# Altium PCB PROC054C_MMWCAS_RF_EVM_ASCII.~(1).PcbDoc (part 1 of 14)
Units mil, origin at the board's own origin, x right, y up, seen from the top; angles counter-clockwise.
Board outline 6299.21 x 5370.07 mil, 8 copper layers (L1 TOP, L2 GND, L3 SIGNAL 1, L4 GND, L5 SIGNAL 2, L6 SIGNAL 3, L7 GND, L8 BOTTOM), stack 53.5 mil thick; 775 components, 552 nets, 2648 pads, 7845 vias.
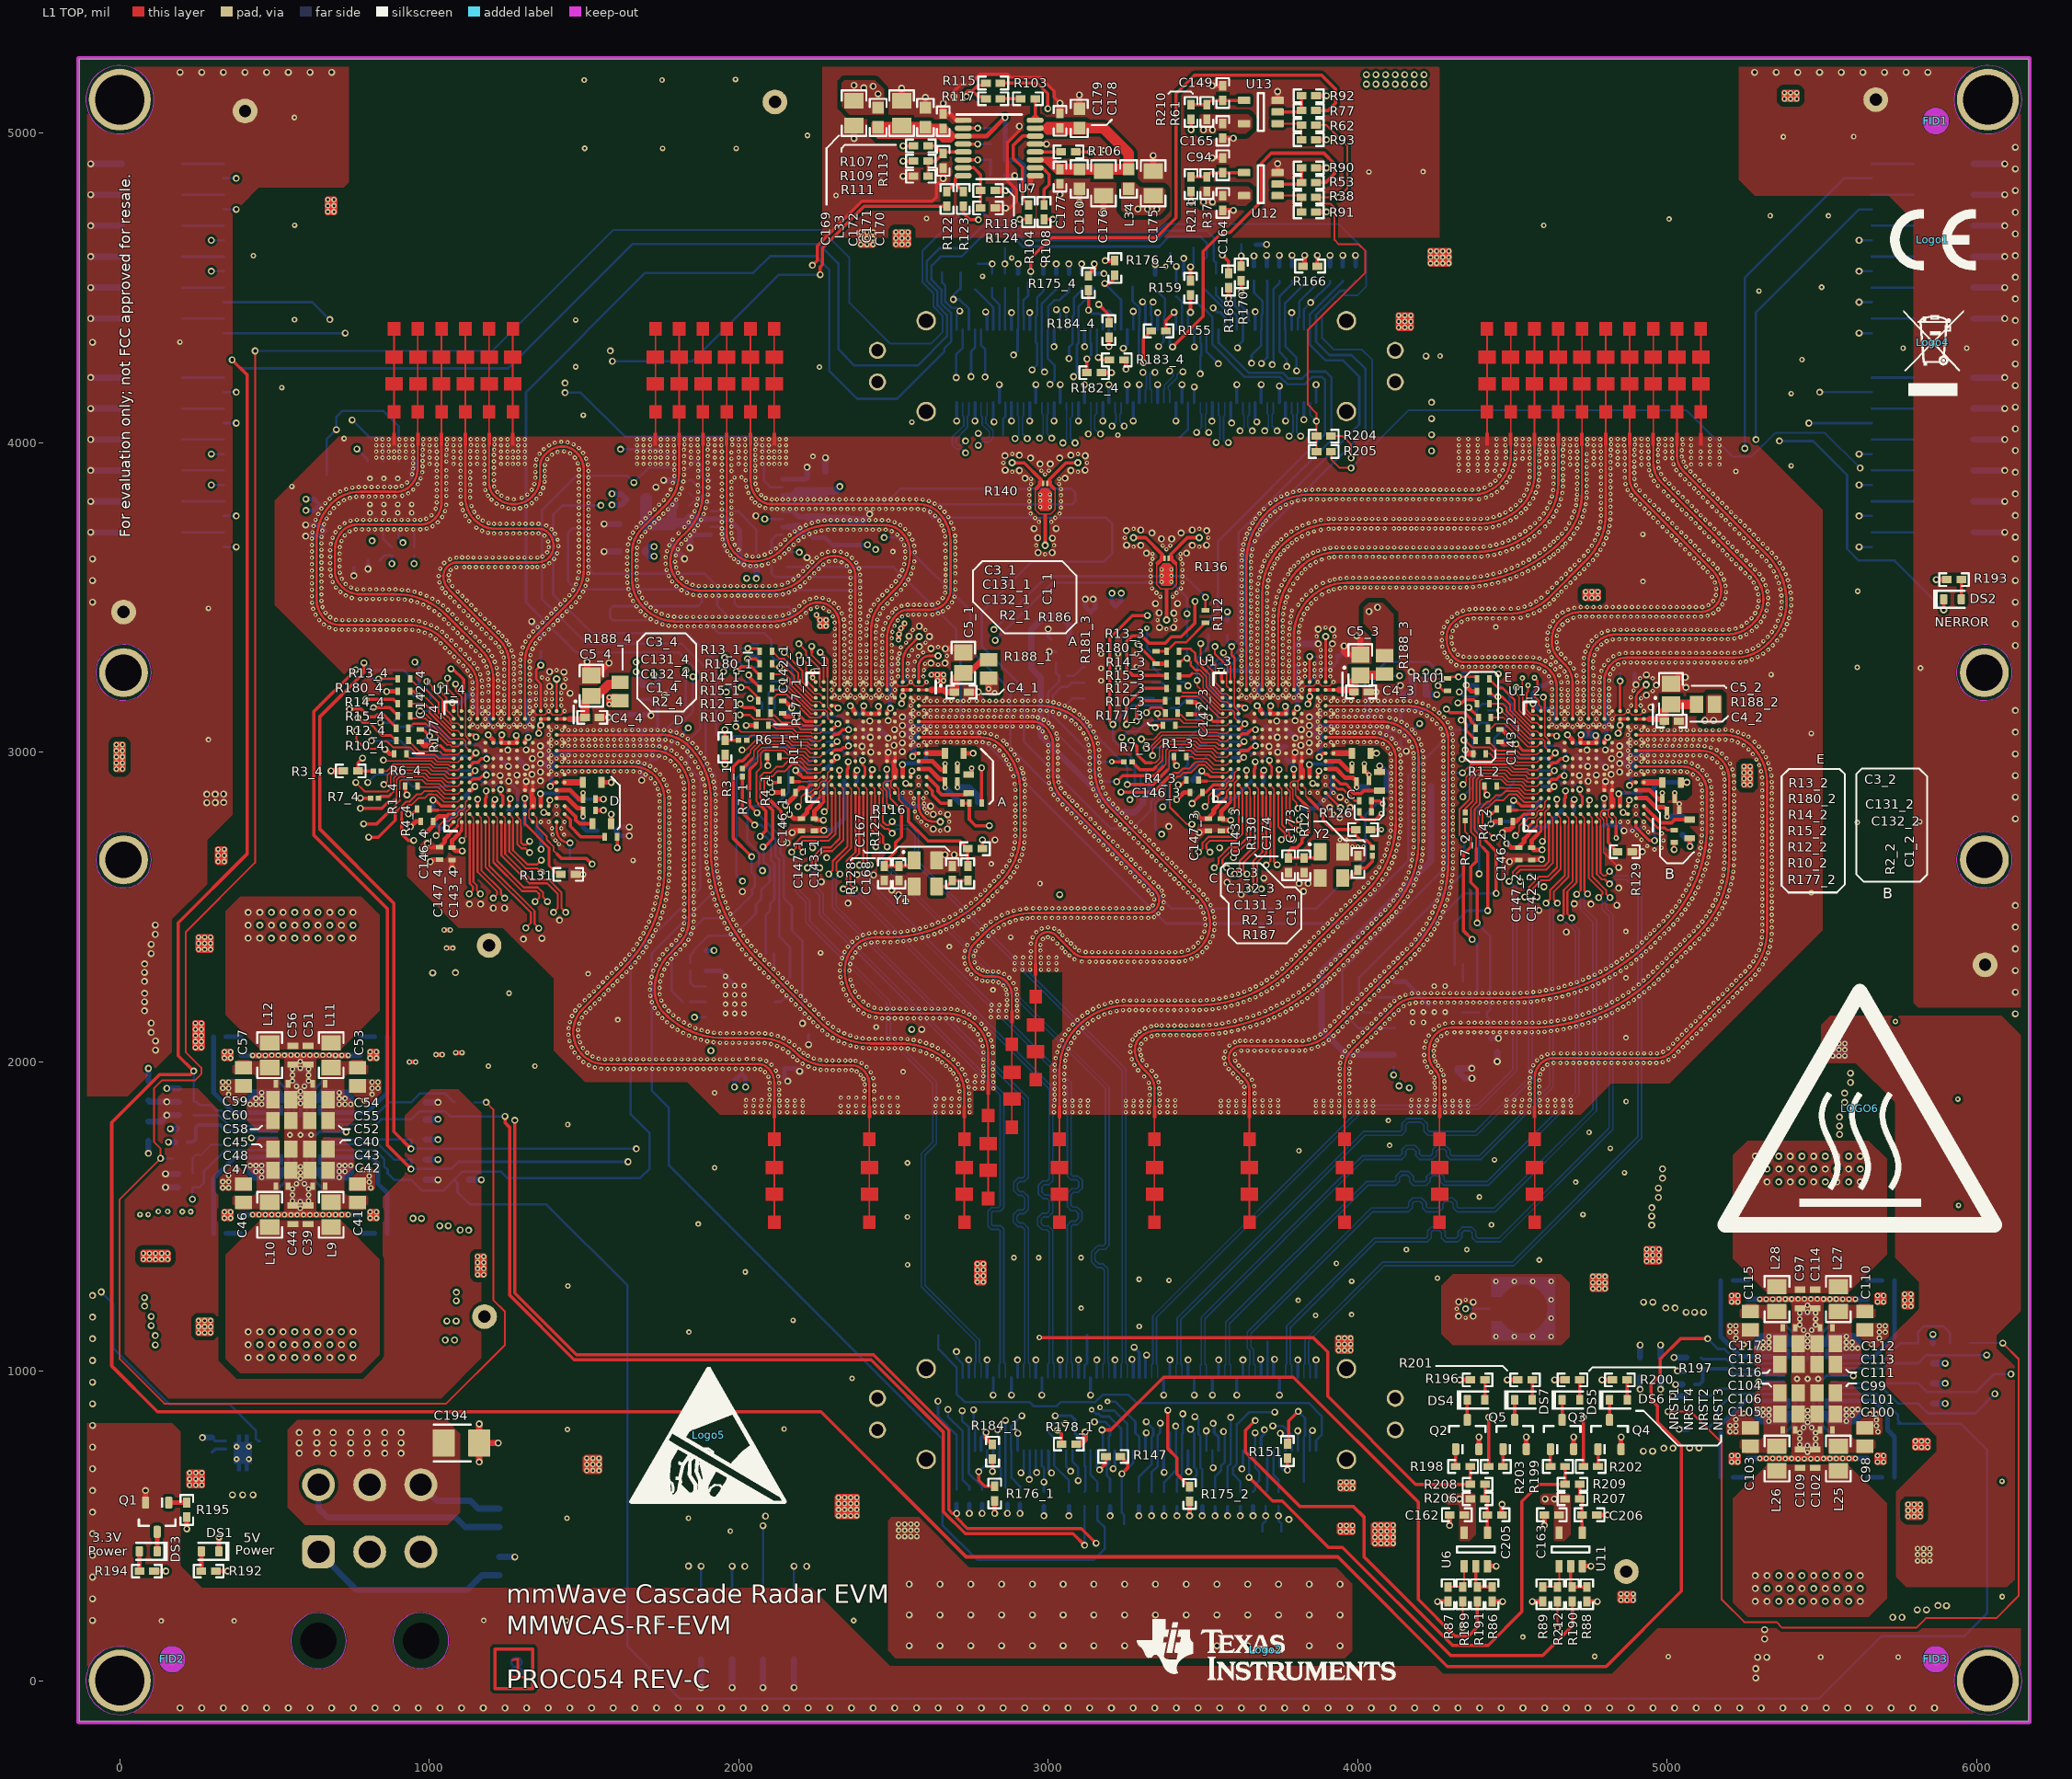
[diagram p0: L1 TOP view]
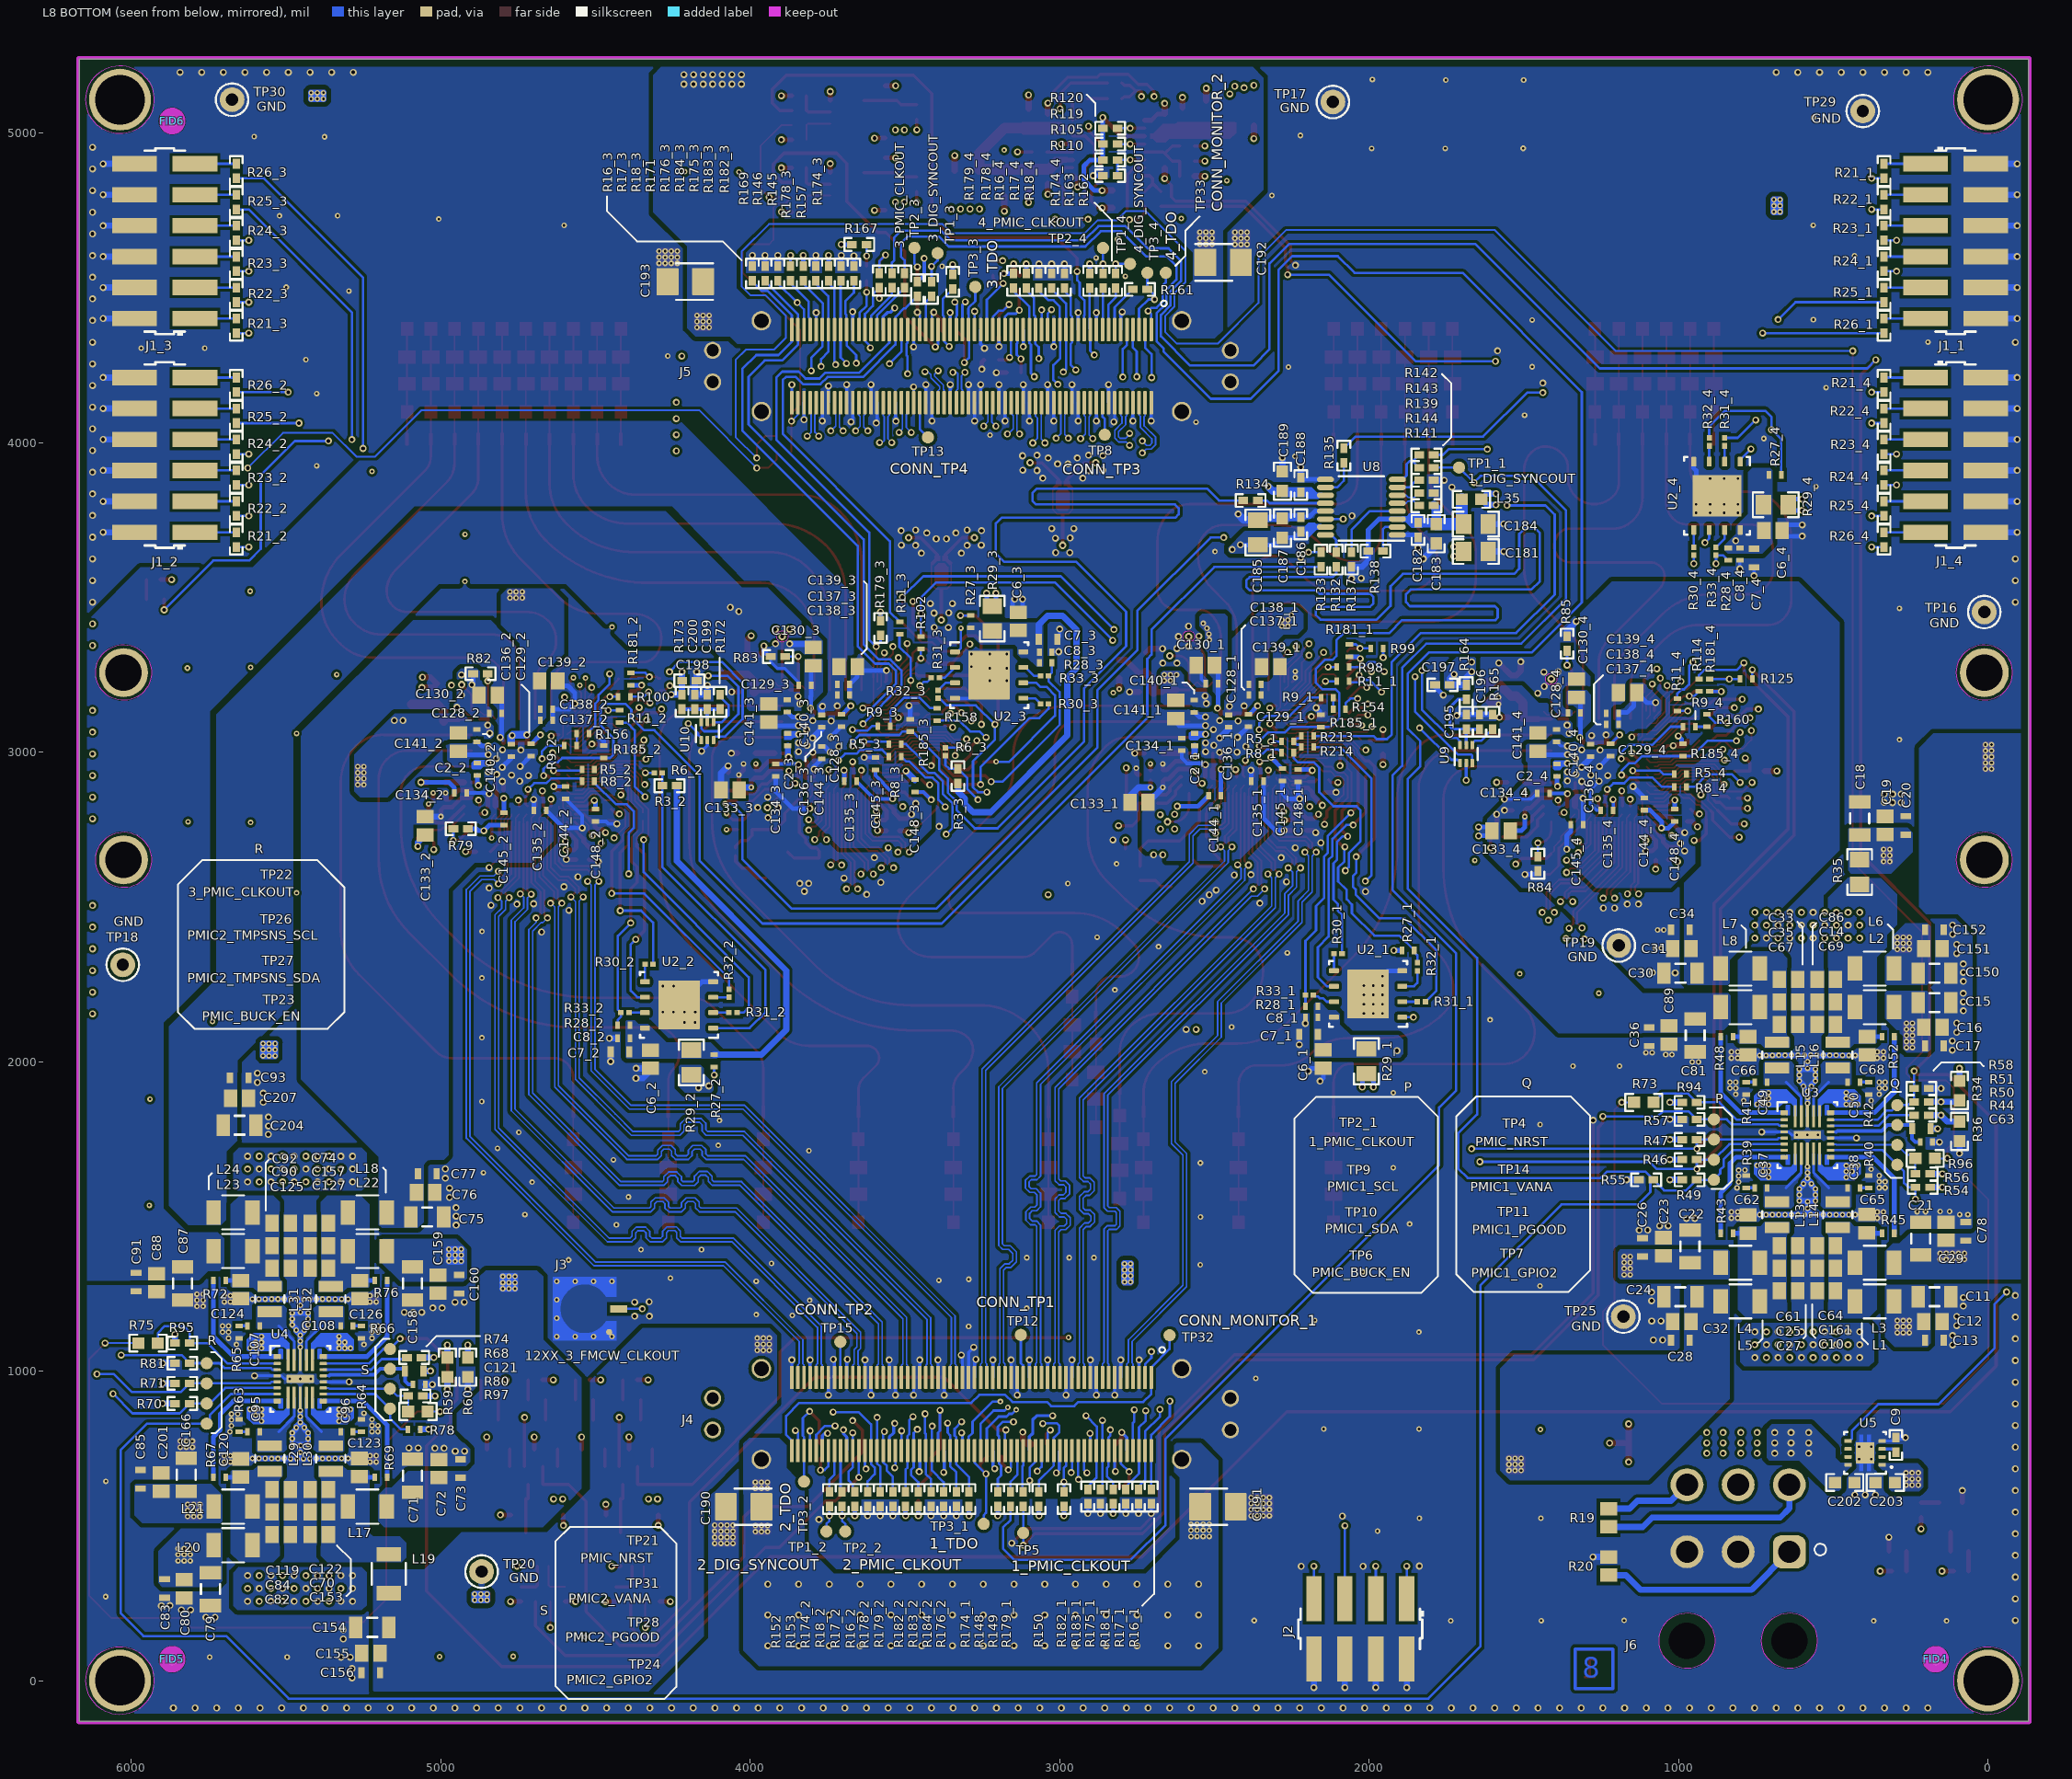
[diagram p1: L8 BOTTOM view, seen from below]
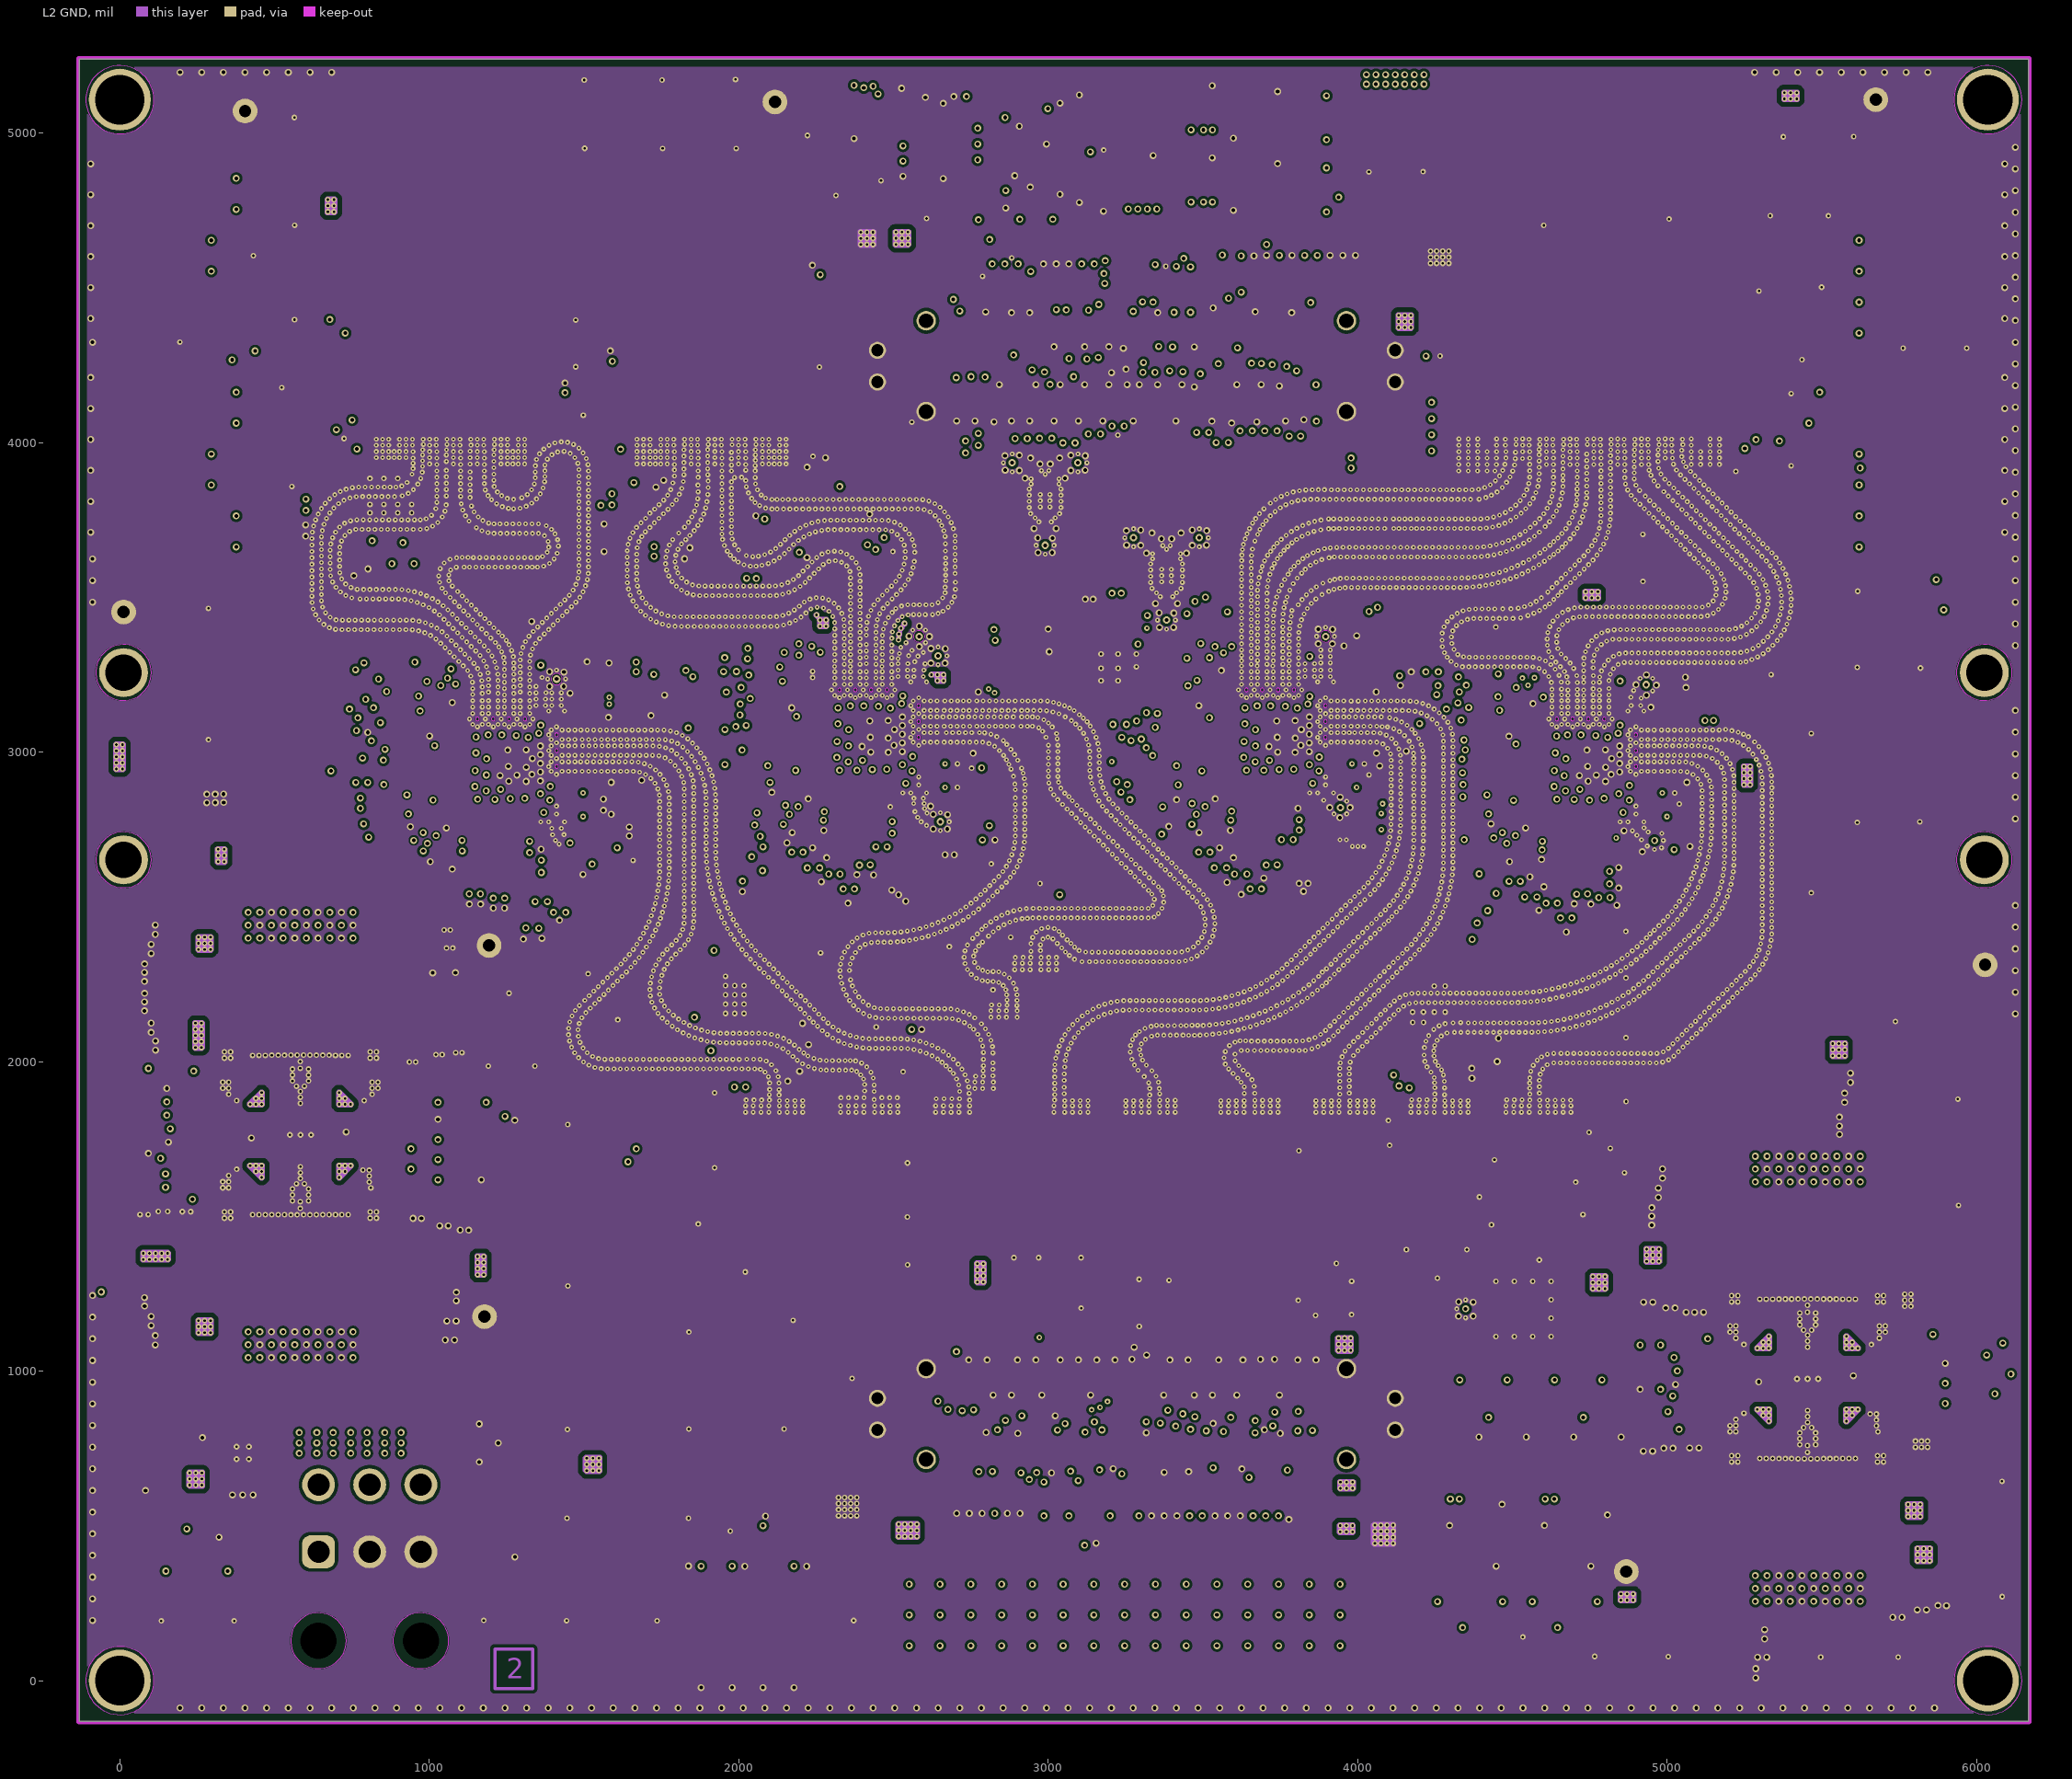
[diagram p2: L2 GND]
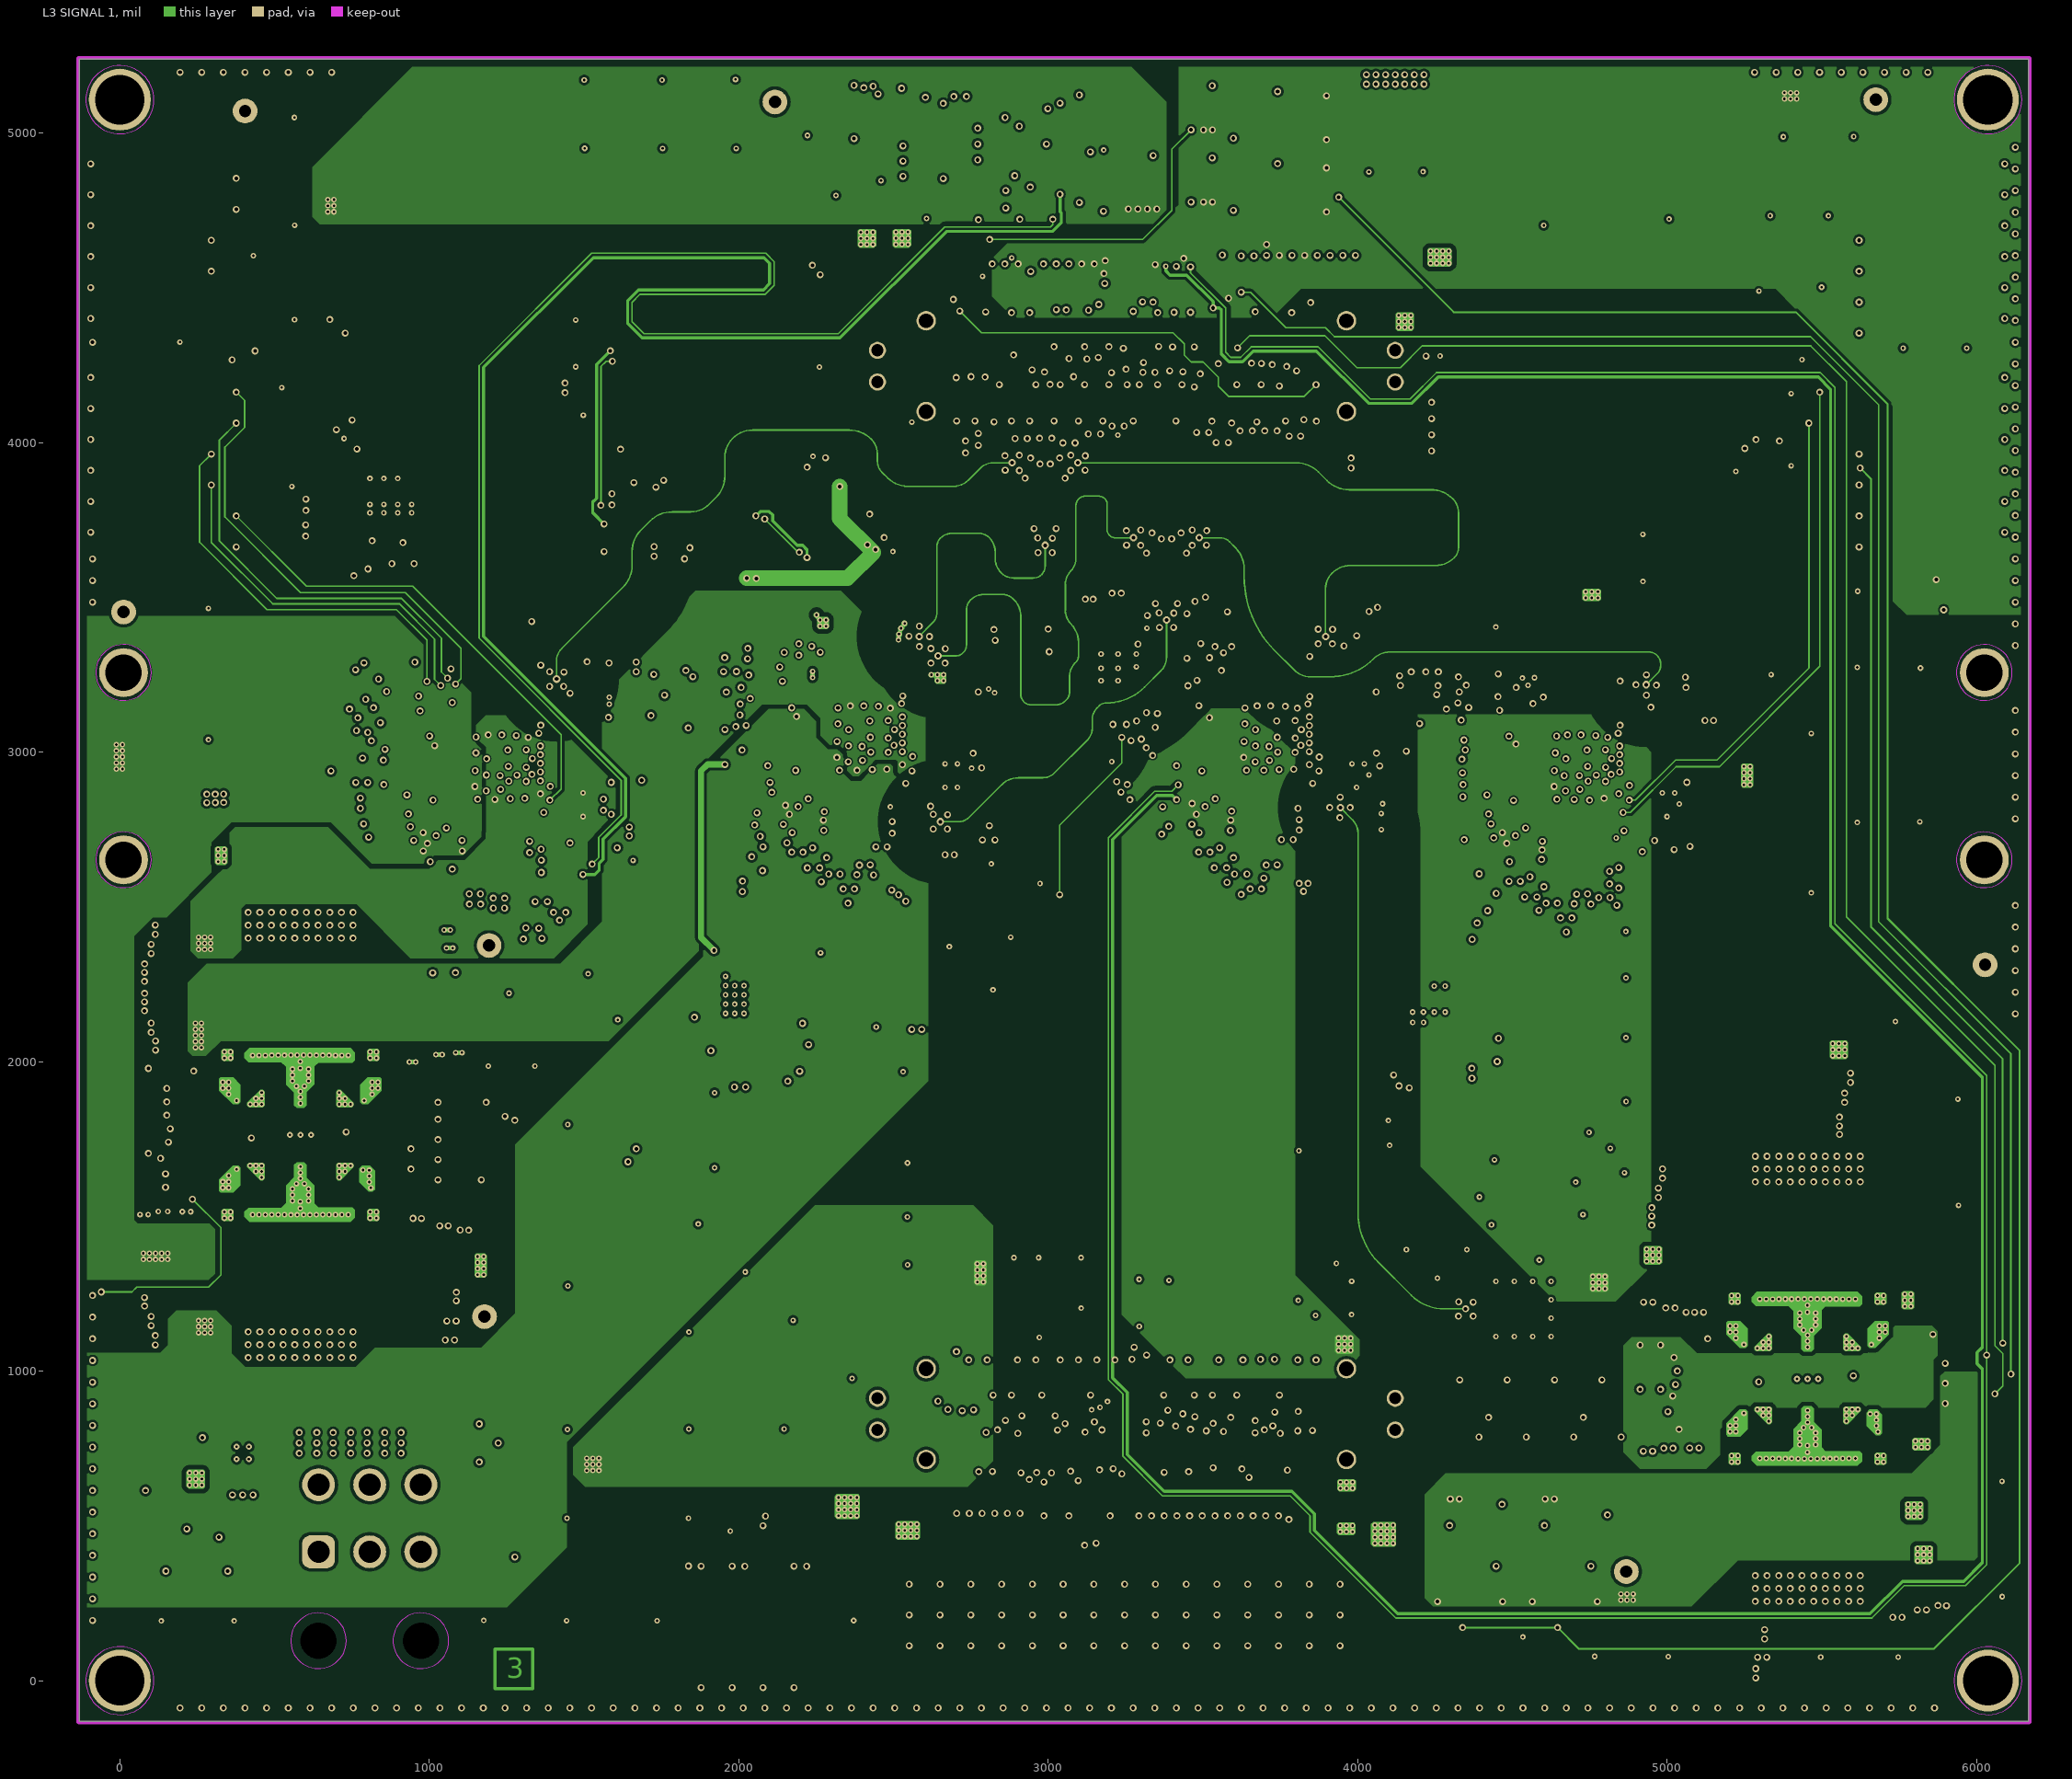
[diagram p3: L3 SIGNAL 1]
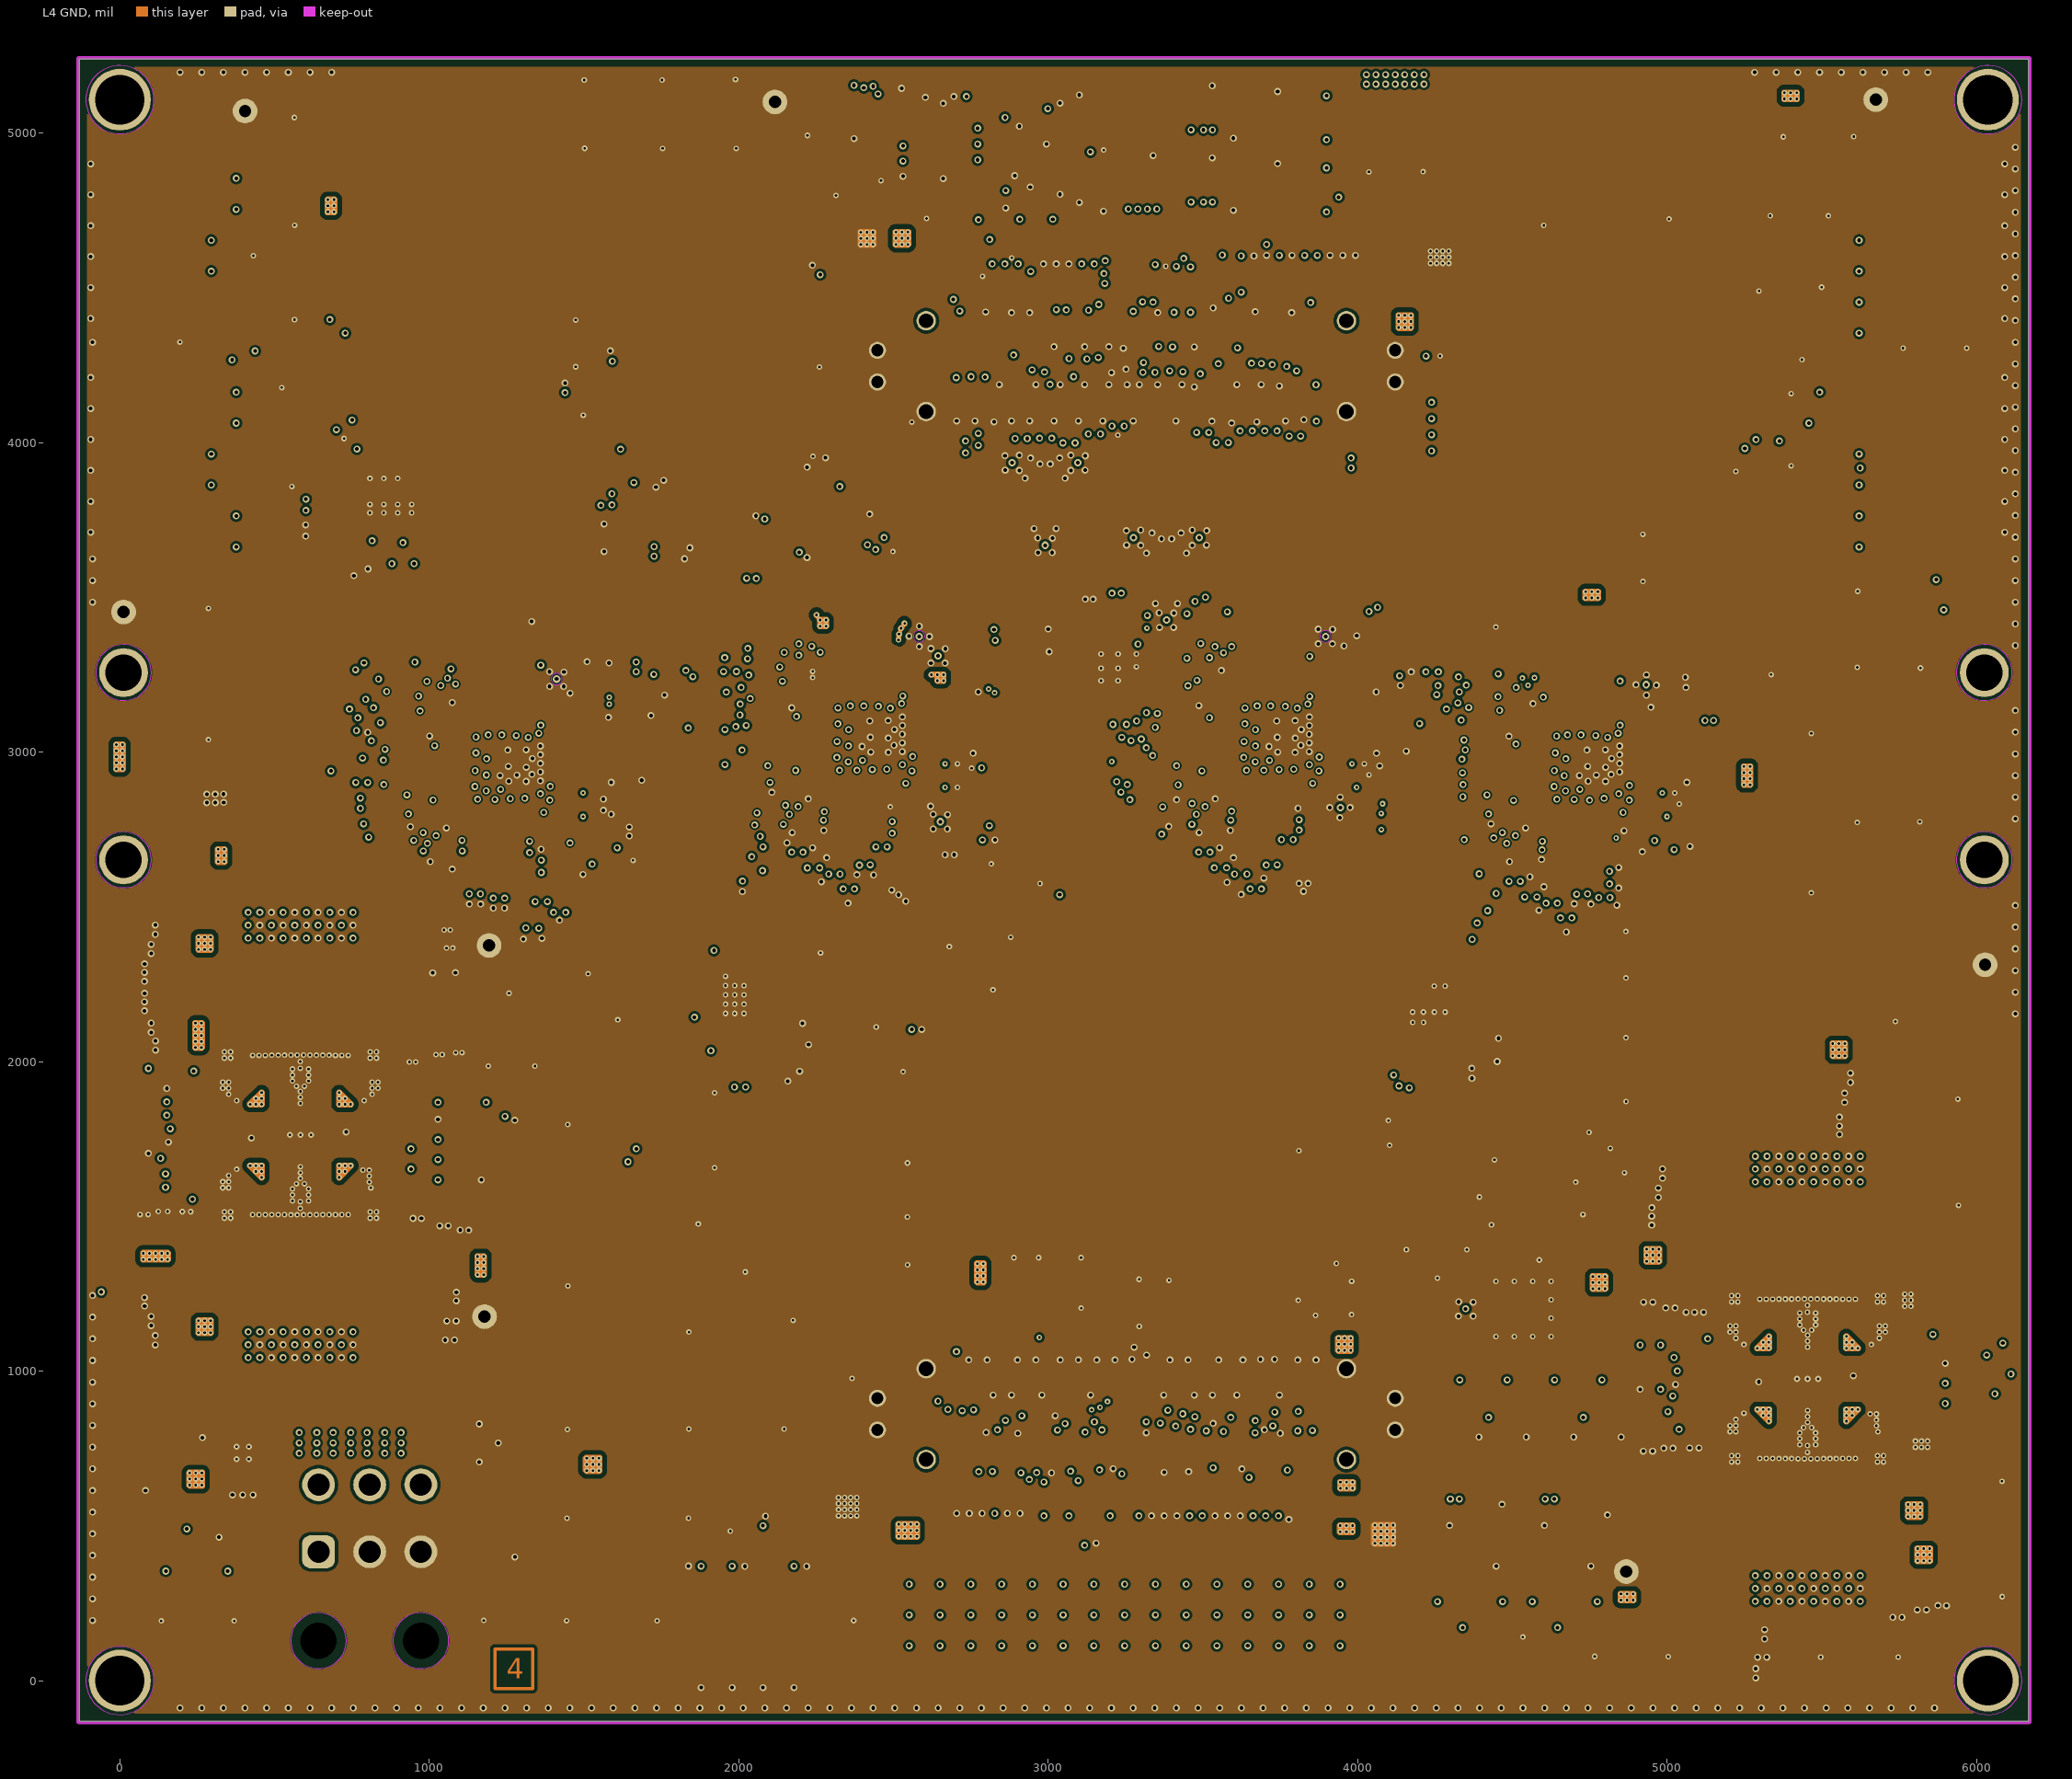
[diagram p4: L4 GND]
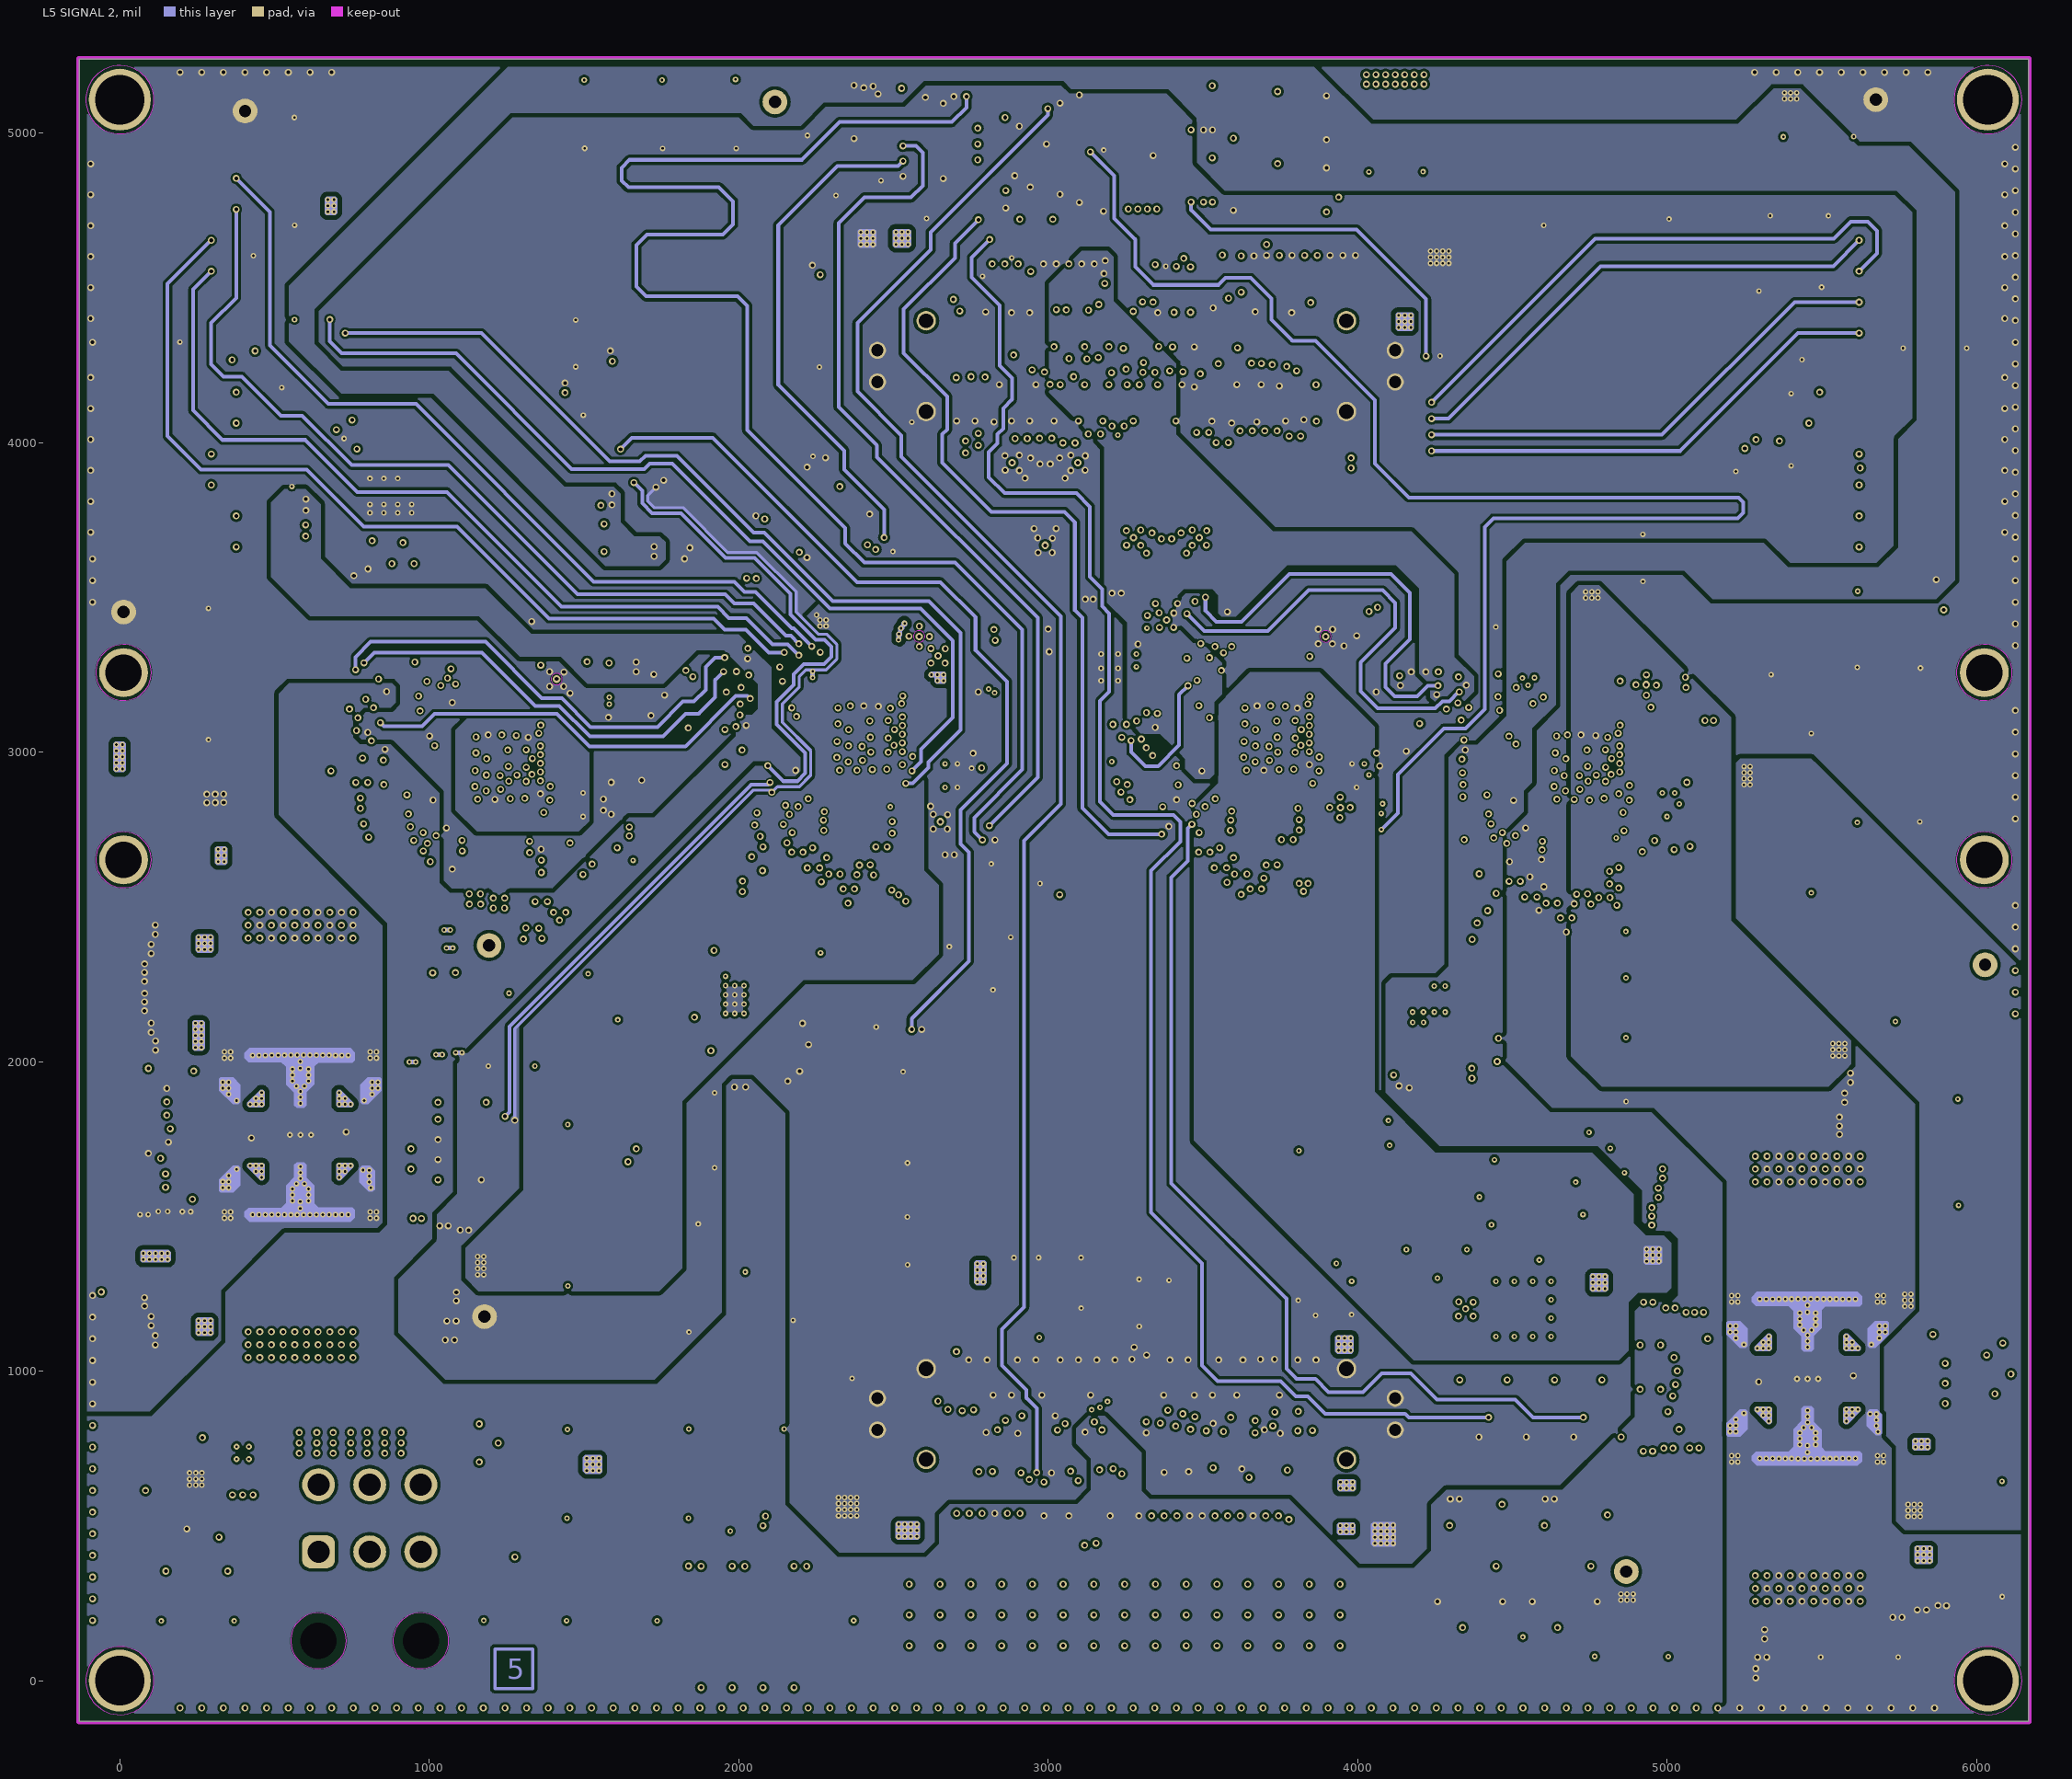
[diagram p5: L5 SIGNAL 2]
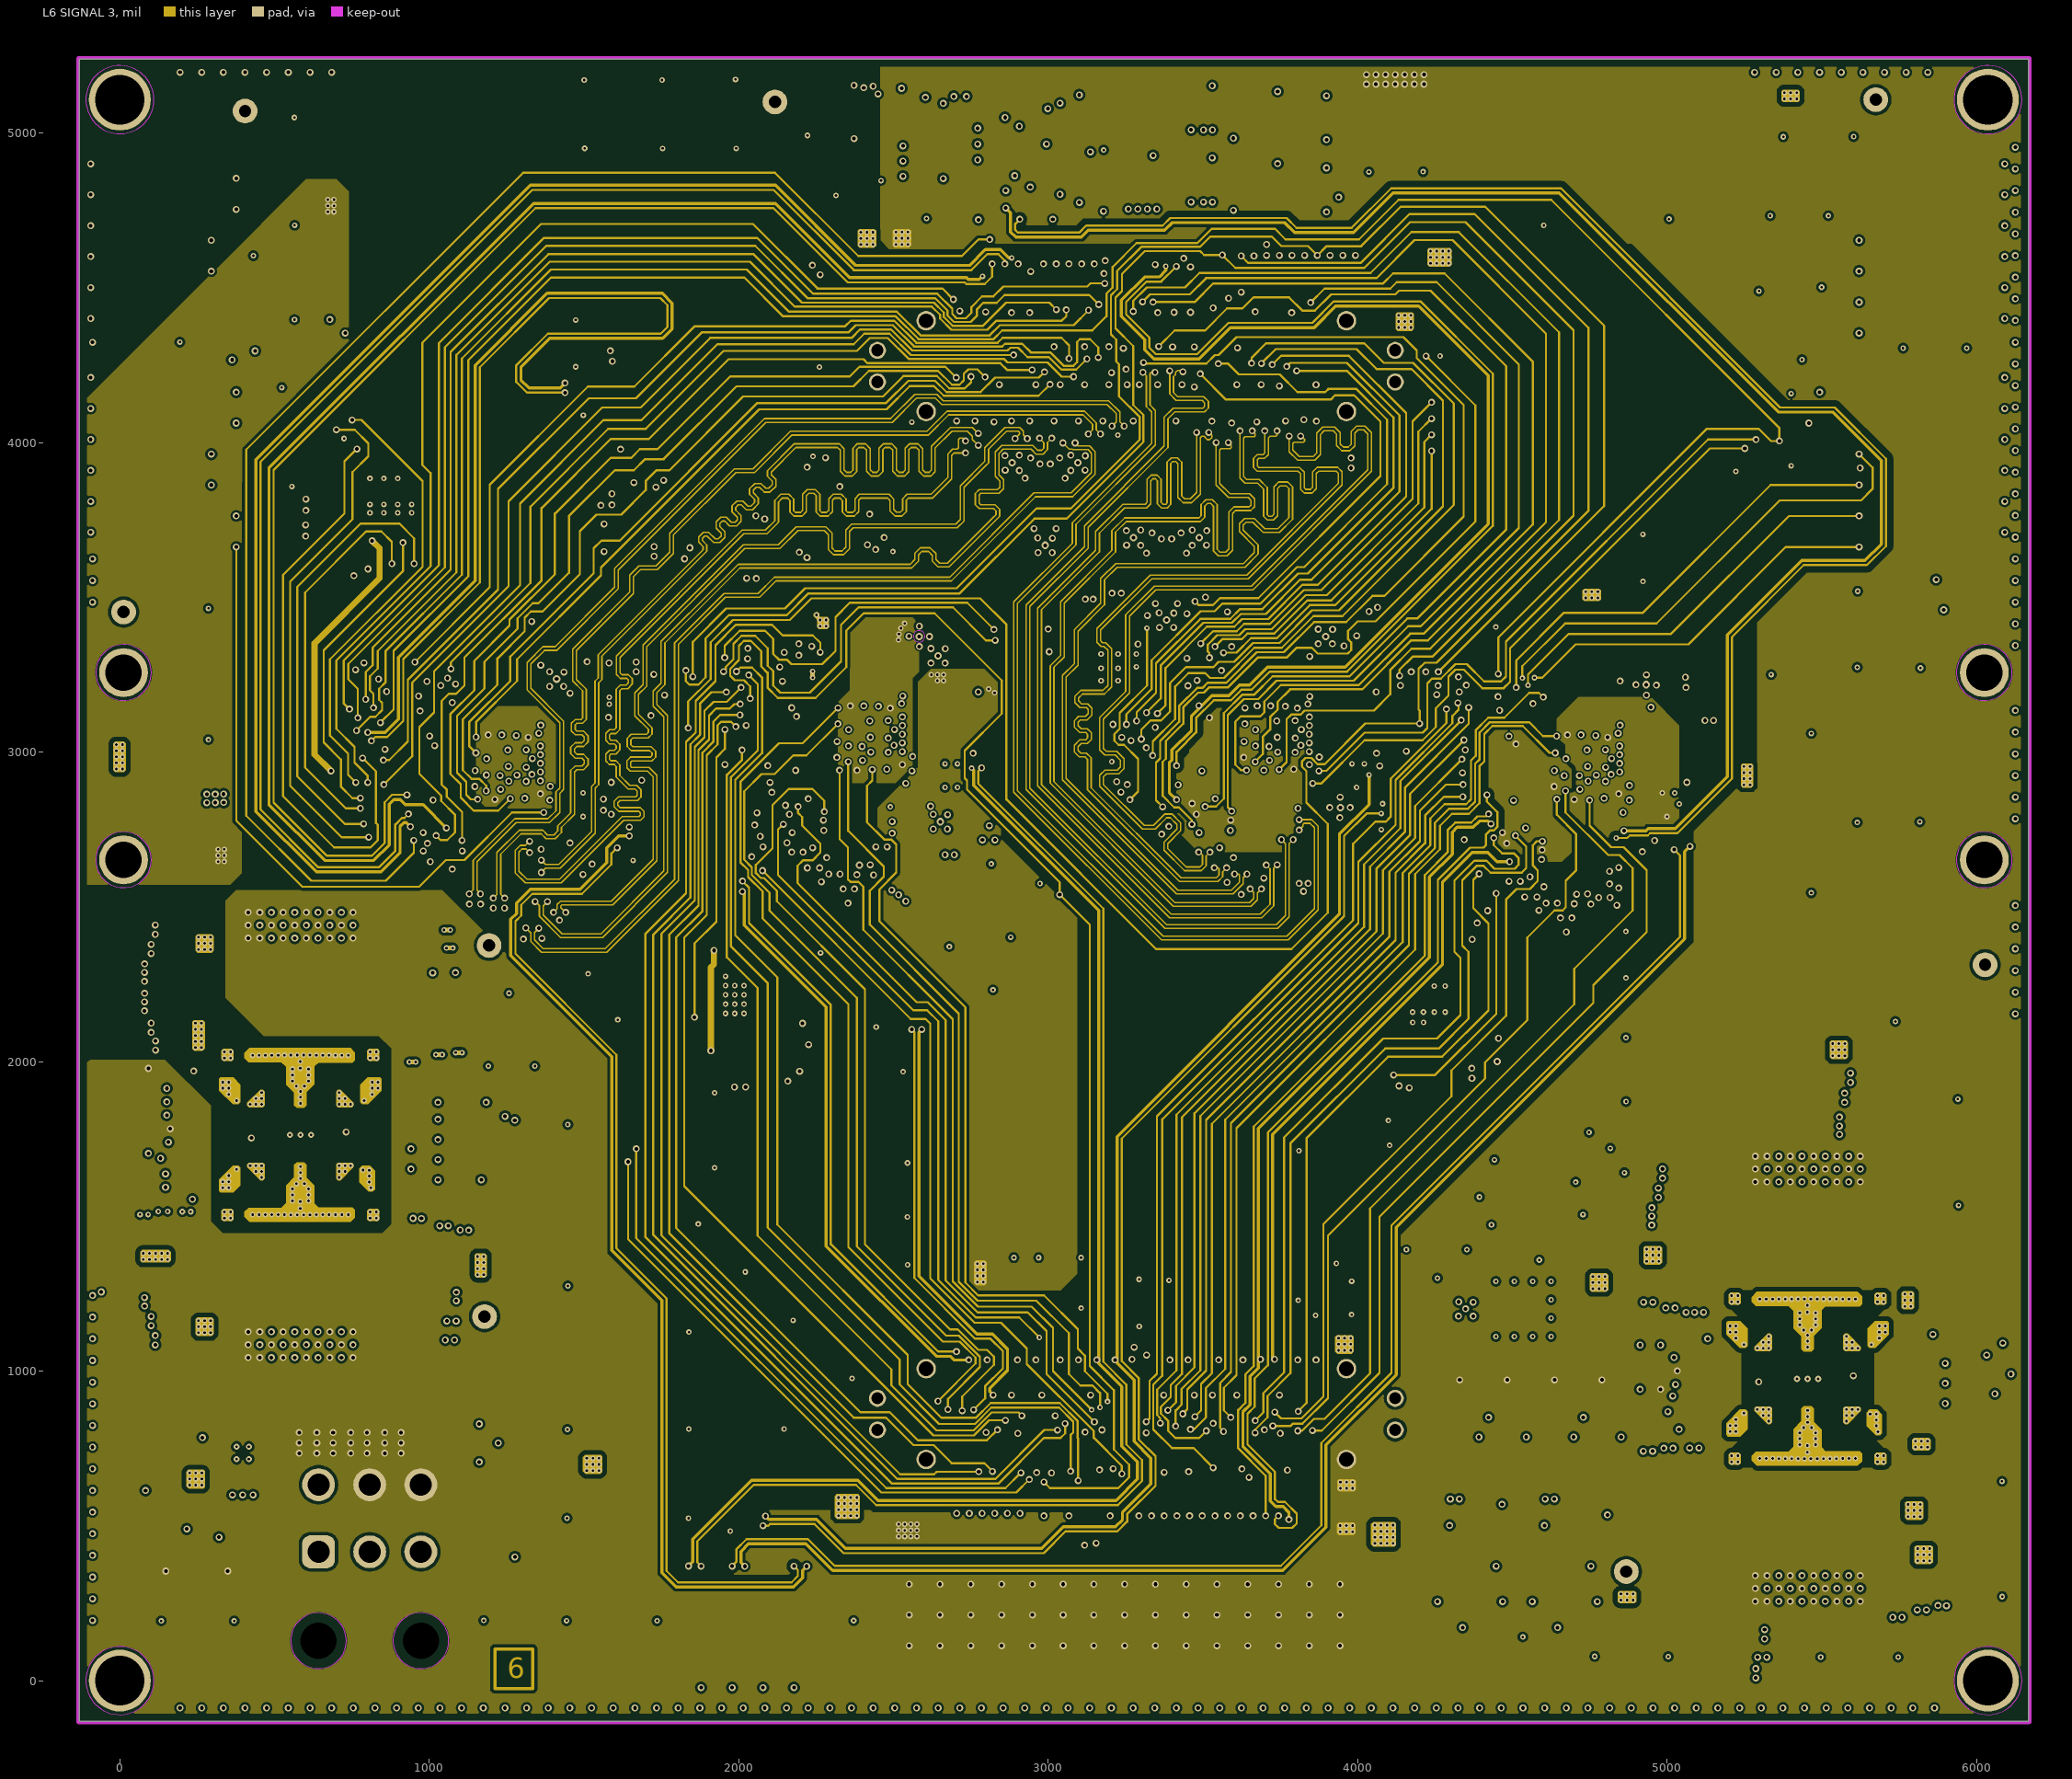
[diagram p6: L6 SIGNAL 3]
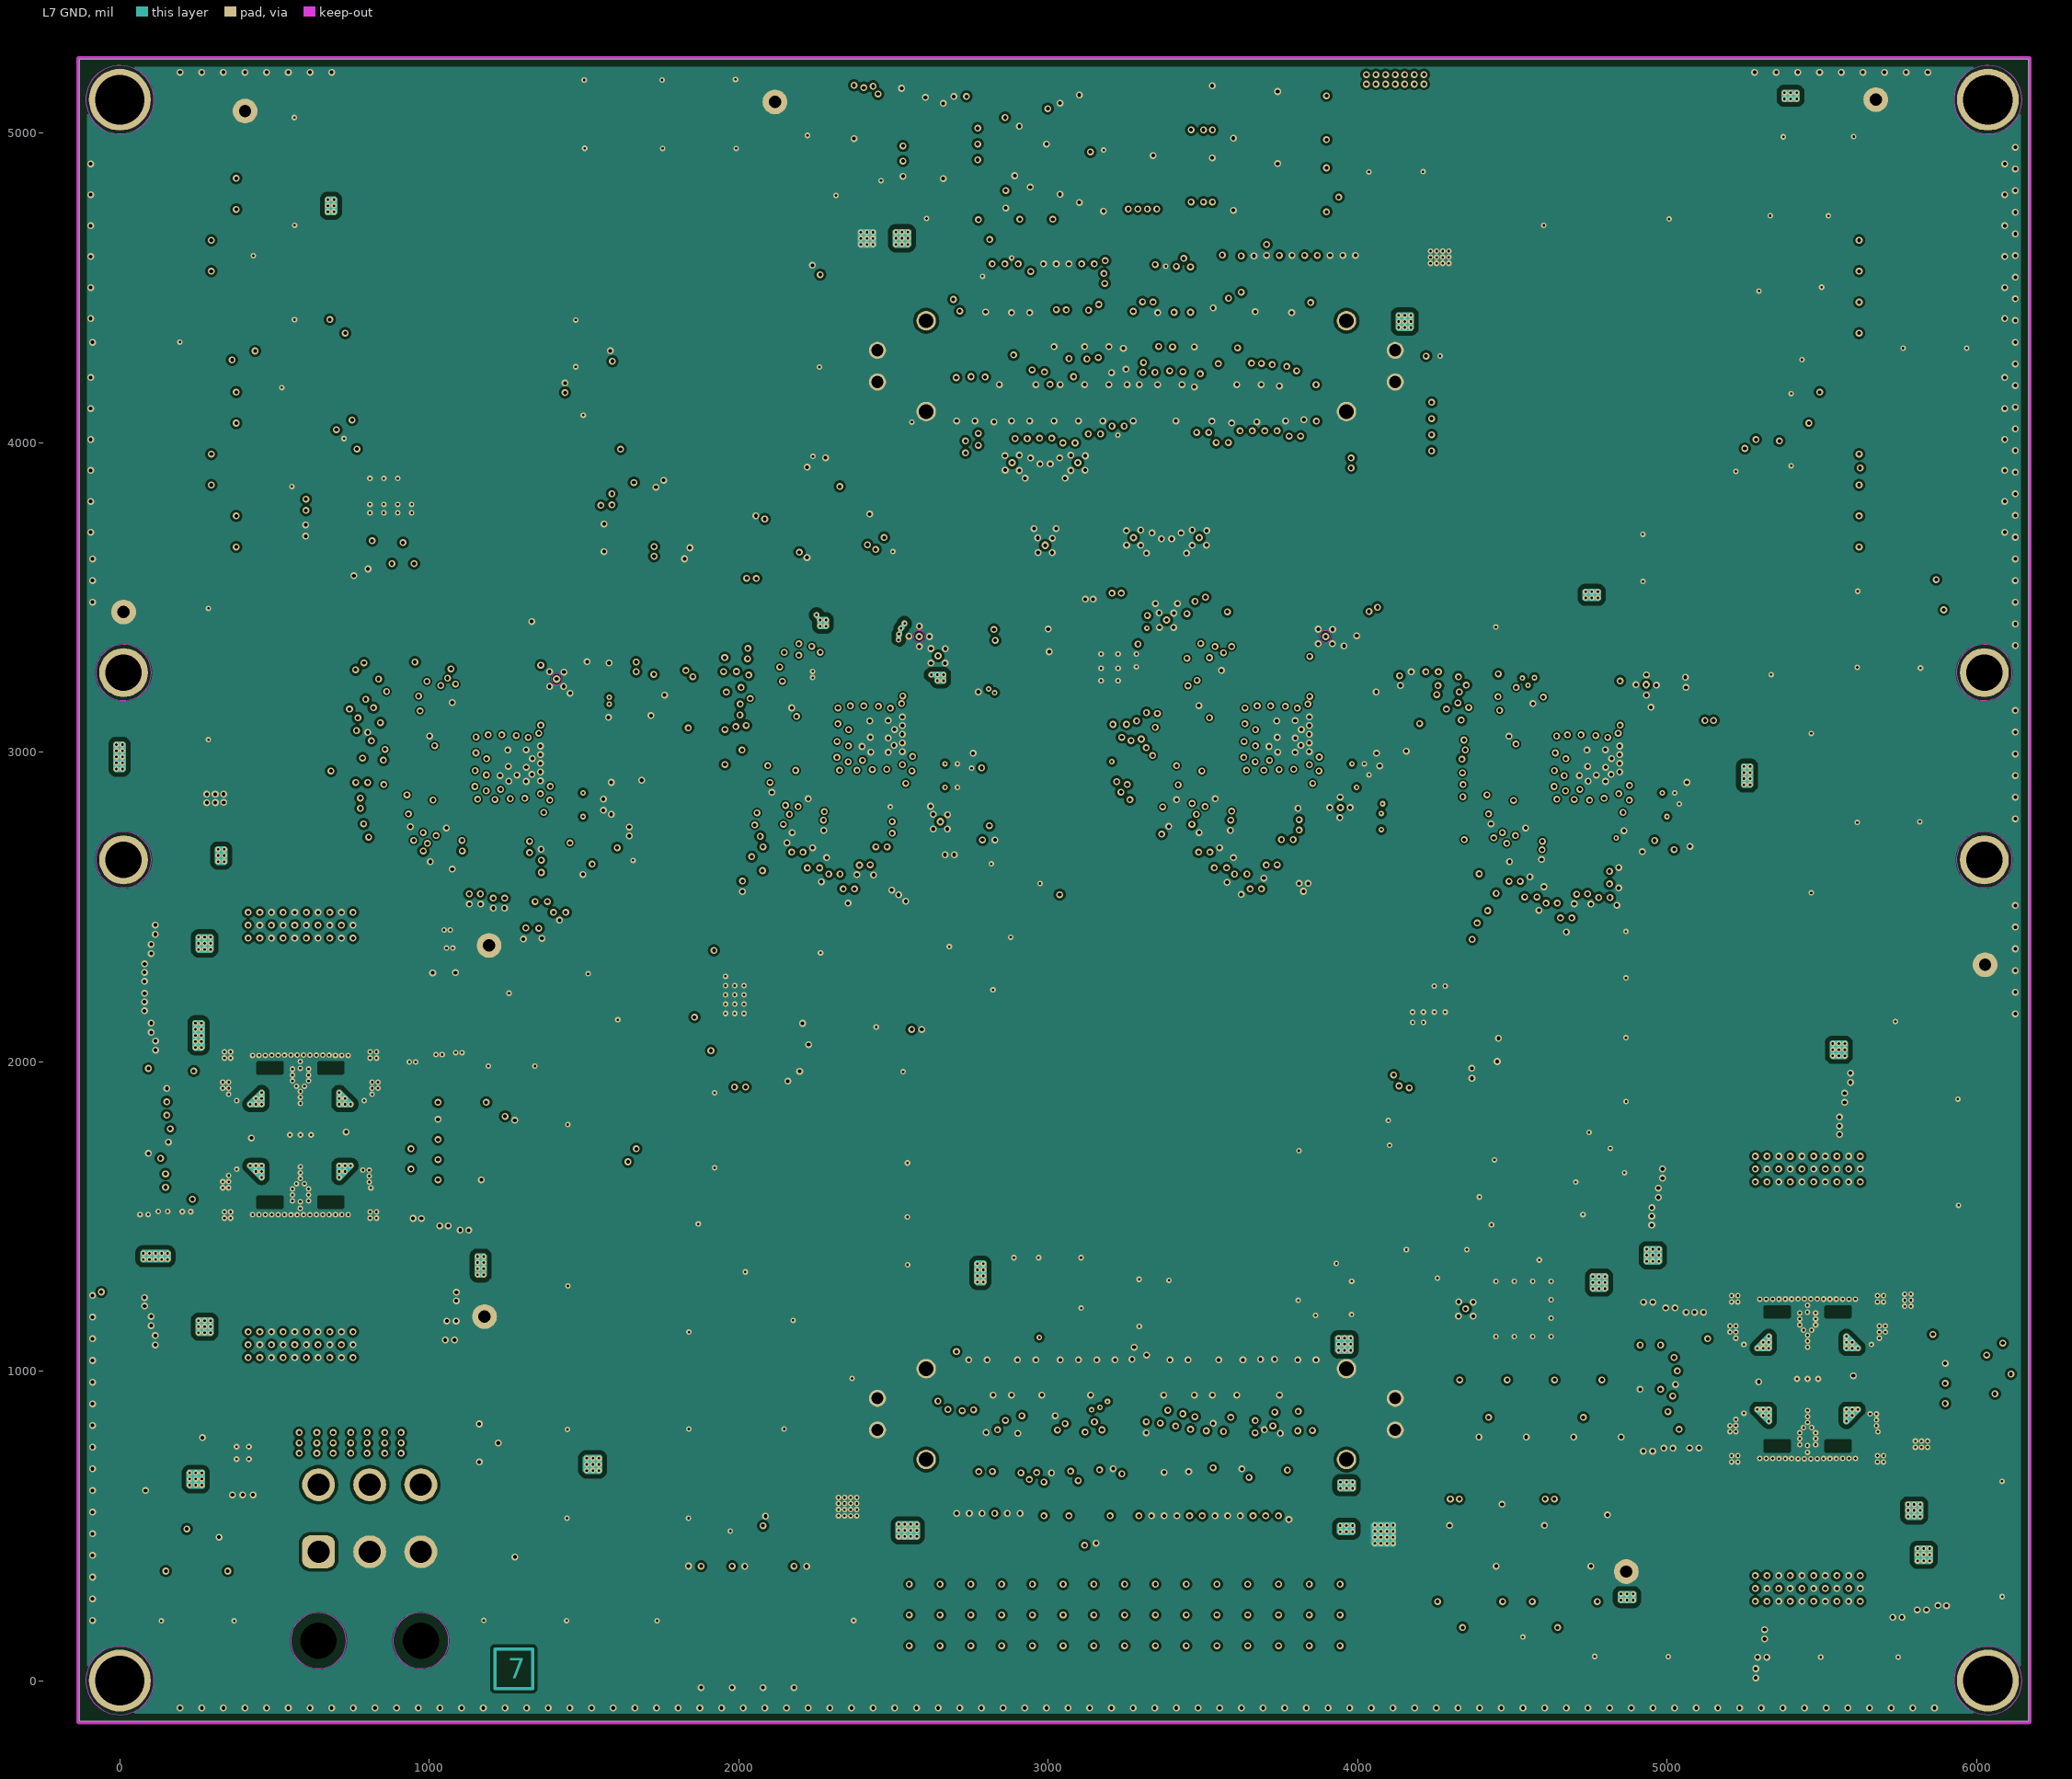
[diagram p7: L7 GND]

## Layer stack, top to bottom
Top Solder: solder mask 0.8, Solder Resist, Dk 3.5
L1 TOP: signal copper 1.6
Dielectric 1: core 5, RO3003, Dk 3
L2 GND: signal copper 0.8
Dielectric2: prepreg 5, RO4450F, Dk 4.2
L3 SIGNAL 1: signal copper 0.6
Dielectric3: core 10.7, RO4835 LOPRO, Dk 3.66
L4 GND: signal copper 0.6
Dielectric4: prepreg 5, 370HR, Dk 4.2
L5 SIGNAL 2: signal copper 1.2
Dielectric5: core 10, 370HR, Dk 4.34
L6 SIGNAL 3: signal copper 0.6
Dielectric6: prepreg 5, 370HR, Dk 4.2
L7 GND: signal copper 0.8
Dielectric7: core 5, 370HR, Dk 4.34
L8 BOTTOM: signal copper 1.6
Bottom Solder: solder mask 0.8, Solder Resist, Dk 3.5

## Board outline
-131,-131 6168.21,-131 6168.21,5239.07 -131,5239.07

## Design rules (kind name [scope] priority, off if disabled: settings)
AcuteAngle [All] p1: minimum=4.00000000000000E+0001 checktracksonly=TRUE
BoardOutlineClearance [All] p1: gap=25 ignorepadtopadclearanceinfootprint=FALSE except(0: Text-OutlineEdge Text-CavityEdge Text-CutoutEdge Text-SplitBarrior Text-SplitContinuation)
Clearance Clearance_TX_RX [(InNetClass('TX') or InNetClass('RX')) and (istrack or IsArc or IsRegion) vs isvia] p1: gap=4 ignorepadtopadclearanceinfootprint=TRUE
Clearance Clearance_L3_4W [istrack and (InNetClass('12XX_CLOCK') or InNetClass('12XX_SYNC')) vs InLayerClass('L3') and inpoly] p2: gap=15.3 ignorepadtopadclearanceinfootprint=TRUE
Clearance Clearance_L6_4W [istrack and (InNetClass('12XX_CLOCK') or InNetClass('12XX_SYNC')) vs InLayerClass('L6') and inpoly] p3: gap=21 ignorepadtopadclearanceinfootprint=TRUE
Clearance Clearance_L8_4W [istrack and (InNetClass('12XX_CLOCK') or InNetClass('12XX_SYNC')) vs InLayerClass('Bottom') and inpoly and not InNet('GND')] p4: gap=23.5 ignorepadtopadclearanceinfootprint=TRUE
Clearance Clearance_GND-Pad [(WithinRoom('GND_Rule1') or WithinRoom('GND_Rule2') or WithinRoom('GND_Rule3') or WithinRoom('GND_Rule4')) and IsPad vs InPoly] p5: gap=9 ignorepadtopadclearanceinfootprint=TRUE
Clearance Clearance_L8_Diff_4W [InAnyDifferentialPair and IsTrack vs Istrack and InLayerClass('Bottom')] p6: gap=21 ignorepadtopadclearanceinfootprint=TRUE
Clearance Clearance_L6_Diff_4W [InAnyDifferentialPair and IsTrack vs Istrack and InLayerClass('L6')] p7: gap=16 ignorepadtopadclearanceinfootprint=TRUE
Clearance "Clearance_Power Divider_1" [isvia and InNetClass('FMCW') and (WithinRoom('Room5') OR WithinRoom('Room6')) vs InNet('GND') and InLayerClass('Top')  and InPoly] p8: gap=8 ignorepadtopadclearanceinfootprint=TRUE except(8.01: Via-Poly)
Clearance "Clearance_Power Divider" [InLayerClass('Top') and All and (WithinRoom('Room5') or WithinRoom('Room6'))] p9: gap=7 ignorepadtopadclearanceinfootprint=TRUE except(4.6: Via-Region; 5.9: Track-Via; 6.6: SMDPad-Poly SMDPad-Region; 8.01: Via-Poly)
Clearance Clearance_FMCW_L3_All_Room [InNetClass('FMCW') and (istrack or IsArc)  and InLayerClass('L3') vs IsVia and (WithinRoom('A1') or WithinRoom('A2') or WithinRoom('A3') or WithinRoom('A4') or WithinRoom('A5') or WithinRoom('A6') or WithinRoom('A7') or WithinRoom('A8') or WithinRoom('A9'))] p10: gap=8 ignorepadtopadclearanceinfootprint=TRUE
Clearance Clearance_FMCW_L3_All [InNetClass('FMCW') and (istrack or IsArc)  and InLayerClass('L3')] p11: gap=50 ignorepadtopadclearanceinfootprint=TRUE except(200: Arc-Poly Track-Poly)
Clearance Clearance_20GHz [IsRegion and InNetClass('20GHz') vs InPoly and InNet('GND')] p12: gap=7 ignorepadtopadclearanceinfootprint=TRUE
Clearance "Clearance_Internal Poly" [InPoly and InLayerClass('Internal') vs isvia and (WithinRoom('Room1') or WithinRoom('Room2') or WithinRoom('Room3') or WithinRoom('Room4'))] p13: gap=5 ignorepadtopadclearanceinfootprint=TRUE
Clearance Clearance_FMCW_L3_Poly [InLayerClass('L3') and InPoly vs (isarc or istrack) AND InNetClass('FMCW')] p14: gap=200 ignorepadtopadclearanceinfootprint=TRUE
Clearance Clearance_Keepout [IsKeepOut] p15: gap=1 ignorepadtopadclearanceinfootprint=TRUE except(0: Arc-SMDPad)
Clearance Clearance_Antenna [InNetClass('Antenna') vs InPoly and InNet('GND') and InLayerClass('Top')] p16: gap=10 ignorepadtopadclearanceinfootprint=FALSE except(4.16: Arc-Poly Track-Poly; 4.69: Poly-Region; 8.01: Via-Poly)
Clearance Clearance_Poly [All vs InPolygon] p17: gap=10 ignorepadtopadclearanceinfootprint=FALSE except(8: Via-Poly; 15: Poly-Poly Poly-Region)
Clearance Clearance_BGA [(WithinRoom('Room1') or WithinRoom('Room2') or WithinRoom('Room3') or WithinRoom('Room4')) and All] p18: gap=4 ignorepadtopadclearanceinfootprint=TRUE
Clearance [All] p19: gap=5 ignorepadtopadclearanceinfootprint=TRUE
DiffPairsRouting [All] p1: maxlimit=10 minlimit=5.5 mostfreqgap=7 toplayer_maxgap=5.5 toplayer_prefgap=5.5 toplayer_minwidth=4 toplayer_maxwidth=6.5 toplayer_prefwidth=6.5 midlayer1_prefgap=5.5 midlayer1_minwidth=4 midlayer1_maxwidth=15 midlayer1_prefwidth=15 midlayer2_prefgap=5.5 midlayer2_minwidth=4 midlayer2_maxwidth=15 midlayer2_prefwidth=15 midlayer3_prefgap=5.5 midlayer3_minwidth=4 midlayer3_maxwidth=15 midlayer3_prefwidth=15 midlayer4_prefgap=5.5 midlayer4_minwidth=4 midlayer4_maxwidth=15 midlayer4_prefwidth=15 midlayer5_mingap=7 midlayer5_maxgap=7 midlayer5_minwidth=5 midlayer5_maxwidth=5 midlayer5_prefwidth=5 midlayer6_prefgap=5.5 midlayer6_minwidth=4 midlayer6_maxwidth=15 midlayer6_prefwidth=15 bottomlayer_mingap=6.75 bottomlayer_maxgap=6.75 bottomlayer_prefgap=6.75 bottomlayer_minwidth=5.25 bottomlayer_maxwidth=5.25 bottomlayer_prefwidth=5.25 maxuncoupledlength=500
HoleSize [All] p1: absolutevalues=TRUE maxlimit=200 minlimit=5.9 maxpercent=80.000 minpercent=20.000
MinimumAnnularRing MinimumAnnularRing_Via [IsVia] p1: minimumring=3.9
MinimumAnnularRing [All] p2: minimumring=7.5
MinimumSolderMaskSliver [All] p1: minsoldermaskwidth=4
PlaneConnect [All] p1: planeconnectstyle=Direct reliefexpansion=20 reliefentries=4 reliefconductorwidth=10 reliefairgap=10
PolygonConnect [All] p1: connectstyle=Direct reliefconductorwidth=25 reliefentries=4 polygonreliefangle="90 Angle" airgapwidth=10
RoomDefinition Room1 [InComponentClass('12XX_4')] p1: confinementstyle=ConfineIn formatcopy=TRUE lockcomponents=FALSE outline 2033.68,3387.07 2640.06,3387.07 2640.06,2735.55 2033.68,2735.55
RoomDefinition Room4 [InComponentClass('Designator')] p2: confinementstyle=ConfineIn formatcopy=TRUE lockcomponents=FALSE outline 852.08,3249.2 1434.07,3249.2 1496.84,3185.76 1496.84,2685.62 852.08,2685.62
RoomDefinition A9 [All] p3: confinementstyle=ConfineOut formatcopy=TRUE lockcomponents=FALSE outline 4145.74,1260.01 4410.11,1260.01 4410.11,1146.81 4145.74,1146.81
RoomDefinition A8 [All] p4: confinementstyle=ConfineOut formatcopy=TRUE lockcomponents=FALSE outline 2598.57,2846.96 2753.75,2846.96 2753.75,2714.54 2598.57,2714.54
RoomDefinition A7 [All] p5: confinementstyle=ConfineOut formatcopy=TRUE lockcomponents=FALSE outline 3895.25,2868.57 4029.93,2868.57 4029.93,2722.5 3895.25,2722.5
RoomDefinition A6 [All] p6: confinementstyle=ConfineOut formatcopy=TRUE lockcomponents=FALSE outline 4876.32,3337.04 5017.79,3337.04 5017.79,3164.57 4876.32,3164.57
RoomDefinition A5 [All] p7: confinementstyle=ConfineOut formatcopy=TRUE lockcomponents=FALSE outline 3835.39,3542.94 3936.51,3542.94 3936.51,3330.51 3835.39,3330.51
RoomDefinition A4 [InComponentClass('Components Class 2')] p8: confinementstyle=ConfineIn formatcopy=TRUE lockcomponents=FALSE outline 3175.56,3808.47 3477.72,3808.47 3591.98,3694.2 3591.98,3647.65 3434.55,3490.22 3434.55,3331.1 3393.93,3290.48 3368.53,3290.48 3338.06,3320.95 3338.06,3457.22 3160.32,3634.96 3160.32,3793.76 3175.58,3809.02
RoomDefinition A3 [InComponentClass('Components Class 1')] p9: confinementstyle=ConfineIn formatcopy=TRUE lockcomponents=FALSE outline 2770.93,3947.31 2798.41,3974.79 3136.7,3974.79 3149.17,3962.32 3149.17,3890.53 3050.37,3791.74 3050.37,3616.18 2992.8,3558.61 2941.62,3558.61 2933.1,3567.14 2933.1,3720.66 2770.71,3883.04 2770.71,3945.66
RoomDefinition A2 [All] p10: confinementstyle=ConfineOut formatcopy=TRUE lockcomponents=FALSE outline 2542.67,3455.84 2644.92,3455.84 2747.67,3353.09 2747.67,3279.13 2680.16,3211.63 2599.75,3211.63 2496.01,3315.37 2496.01,3409.93 2542.15,3456.07
RoomDefinition A1 [All] p11: confinementstyle=ConfineOut formatcopy=TRUE lockcomponents=FALSE outline 1337.09,3340.68 1479.92,3340.68 1479.92,3170.39 1337.09,3170.39
RoomDefinition GND_Rule4 [All] p12: confinementstyle=ConfineOut formatcopy=TRUE lockcomponents=FALSE outline 4866.7,2842.12 4932.23,2842.12 4932.23,2750.95 4866.7,2750.95
RoomDefinition GND_Rule3 [All] p13: confinementstyle=ConfineOut formatcopy=TRUE lockcomponents=FALSE outline 3863.74,2936.22 3929.27,2936.22 3929.27,2845.04 3863.74,2845.04
RoomDefinition GND_Rule1 [All] p14: confinementstyle=ConfineOut formatcopy=TRUE lockcomponents=FALSE outline 1378.19,2850.59 1443.72,2850.59 1443.72,2759.41 1378.19,2759.41
RoomDefinition GND_Rule2 [All] p15: confinementstyle=ConfineOut formatcopy=TRUE lockcomponents=FALSE outline 2551.17,2940.69 2616.7,2940.69 2616.7,2849.52 2551.17,2849.52
RoomDefinition Room6 [InComponentClass('Components Class 2')] p16: confinementstyle=ConfineIn formatcopy=TRUE lockcomponents=FALSE outline 3223.97,3753.59 3539.32,3753.59 3539.32,3383.84 3223.97,3383.84
RoomDefinition Room5 [InComponentClass('Components Class 1')] p17: confinementstyle=ConfineIn formatcopy=TRUE lockcomponents=FALSE outline 2834.35,3978.35 3143.28,3978.35 3143.28,3621.24 2834.35,3621.24
RoomDefinition Room2 [InComponentClass('Designator')] p18: confinementstyle=ConfineIn formatcopy=TRUE lockcomponents=FALSE outline 4337.7,3208.98 4954.79,3208.98 4954.79,2675.33 4337.7,2675.33
RoomDefinition Room3 [InComponentClass('40MHZ_CLOCK')] p19: confinementstyle=ConfineIn formatcopy=TRUE lockcomponents=FALSE outline 3321.42,3391.65 3927.1,3391.65 3927.1,2786.33 3321.42,2786.33
RoutingVias [All] p1: holewidth=28 width=50 viastyle="Through Hole" minholewidth=5.8 minwidth=15 maxholewidth=28 maxwidth=50
SilkToBoardRegionClearance [Not ((IsComment or IsDesignator) And (Hide <> 'False')) and not InRegion(1000,500,4000,800)] p1:
SilkToSilkClearance [All] p1: silktosilkclearance=3
SilkToSolderMaskClearance [IsPad] p1: minsilkscreentomaskgap=3 clearancetoexposedcopper=TRUE
SolderMaskExpansion [All] p1: expansion=0
Width [All] p1: maxlimit=50 minlimit=4 preferedwidth=10
23 further rules are at their usual default settings.

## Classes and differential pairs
net class PMIC_CLKOUT: 12XX_1_PMIC_CLKOUT 12XX_2_PMIC_CLKOUT 12XX_3_PMIC_CLKOUT 12XX_4_PMIC_CLKOUT
net class "GND SENSE": 12XX_1_OSC_CLKOUT 12XX_1_OSC_CLKOUT_CONN 12XX_2_OSC_CLKOUT 12XX_3_OSC_CLKOUT 12XX_3_OSC_CLKOUT_CONN 12XX_4_OSC_CLKOUT BUF_CLKOUT2_RS BUF_CLKOUT3 BUF_CLKOUT3_RS BUF_CLKOUT4_RS EXT_40M_BUF_12XX_1_RS
net class FMCW: 12XX_1_FMCW_CLKOUT 12XX_1_FMCW_SYNCOUT 12XX_3_FMCW_CLKOUT
net class 20GHz: 12XX_2_FMCW_CLKOUT 12XX_2_FMCW_SYNCOUT 12XX_3_FMCW_CLKOUT 12XX_3_FMCW_SYNCOUT 12XX_4_FMCW_CLKOUT 12XX_4_FMCW_SYNCOUT
net class TX: 12XX_TX1_1 12XX_TX1_2 12XX_TX1_3 12XX_TX1_4 12XX_TX2_1 12XX_TX2_2 12XX_TX2_3 12XX_TX2_4 12XX_TX3_1 12XX_TX3_2 12XX_TX3_3 12XX_TX3_4
net class RX: 12XX_RX1_1 12XX_RX1_2 12XX_RX1_3 12XX_RX1_4 12XX_RX2_1 12XX_RX2_2 12XX_RX2_3 12XX_RX2_4 12XX_RX3_1 12XX_RX3_2 12XX_RX3_3 12XX_RX3_4 12XX_RX4_1 12XX_RX4_2 12XX_RX4_3 12XX_RX4_4
net class Non-imp: 12XX_1_1V0_RF1_FILT 12XX_1_1V0_RF2_FILT 12XX_1_1V2_FILT 12XX_1_1V8_FILT 12XX_1_SCL 12XX_1_SDA 12XX_2_1V0_RF1_FILT 12XX_2_1V0_RF2_FILT 12XX_2_1V2_FILT 12XX_2_1V8_FILT 12XX_2_SCL 12XX_2_SDA 12XX_3_1V0_RF1_FILT 12XX_3_1V0_RF2_FILT 12XX_3_1V2_FILT 12XX_3_1V8_FILT 12XX_3_SCL 12XX_3_SDA 12XX_4_1V0_RF1_FILT 12XX_4_1V0_RF2_FILT 12XX_4_1V2_FILT 12XX_4_1V8_FILT 12XX_4_SCL 12XX_4_SDA AR_1V4_APLL_1 AR_1V4_APLL_2 AR_1V4_APLL_3 AR_1V4_APLL_4 AR_VBGAP_1 AR_VBGAP_2 AR_VBGAP_3 AR_VBGAP_4 AR_VOUT_PA_1 AR_VOUT_PA_2 AR_VOUT_PA_3 AR_VOUT_PA_4 GND LMK1_1V8 LMK1_3V3 LMK2_3V3 NetC9_1 NetC37_2 NetC38_2 NetC49_2 NetC50_2 NetC95_2 NetC96_2 NetC107_2 NetC108_2 NetDS3_2 PMIC1_3V3 PMIC1_12XX_1_1V0 PMIC1_12XX_4_1V0 PMIC1_12XX_14_1V2 PMIC1_12XX_14_1V8 PMIC1_FB_B0 PMIC1_FB_B1 PMIC1_FB_B2 PMIC1_FB_B3 PMIC1_INTN PMIC1_PGOOD PMIC1_PGOOD_RS PMIC1_SW_B0 PMIC1_SW_B1 PMIC1_SW_B2 PMIC1_SW_B3 PMIC1_VANA PMIC1_VIN_B0 PMIC1_VIN_B1 PMIC1_VIN_B2 PMIC1_VIN_B3 PMIC2_3V3 PMIC2_12XX_2_1V0 PMIC2_12XX_3_1V0 PMIC2_12XX_23_1V2 PMIC2_12XX_23_1V8 PMIC2_FB_B0 PMIC2_FB_B1 PMIC2_FB_B2 PMIC2_FB_B3 PMIC2_INTN PMIC2_PGOOD PMIC2_PGOOD_RS PMIC2_SW_B0 PMIC2_SW_B1 PMIC2_SW_B2 PMIC2_SW_B3 PMIC2_VANA PMIC2_VIN_B0 PMIC2_VIN_B1 PMIC2_VIN_B2 PMIC2_VIN_B3 QSPI_FLASH_3V3_1 QSPI_FLASH_3V3_2 QSPI_FLASH_3V3_3 QSPI_FLASH_3V3_4 SDA_RS_1 SDA_RS_2 SDA_RS_3 SDA_RS_4 SYSTEM_1V8 SYSTEM_3V3 SYSTEM_3V3_LED SYSTEM_3V3_LED_PW SYSTEM_5V0 SYSTEM_5V0_LED SYSTEM_PGOOD SYSTEM_PGOOD2_GS TMP1_3V3 TMP2_3V3
net class Impedance: 12XX_1_BSS_LOGGER 12XX_1_CSI2_CLK_N 12XX_1_CSI2_CLK_P 12XX_1_CSI2_TX0_N 12XX_1_CSI2_TX0_P 12XX_1_CSI2_TX1_N 12XX_1_CSI2_TX1_P 12XX_1_CSI2_TX2_N 12XX_1_CSI2_TX2_P 12XX_1_CSI2_TX3_N 12XX_1_CSI2_TX3_P 12XX_1_DIG_SYNCIN 12XX_1_DIG_SYNCIN_RS 12XX_1_DIG_SYNCOUT 12XX_1_FMCW_CLKOUT 12XX_1_FMCW_SYNCOUT 12XX_1_GPIO_0 12XX_1_GPIO_1 12XX_1_GPIO_2 12XX_1_LVDS_FRCLK_N 12XX_1_LVDS_FRCLK_P 12XX_1_LVDS_VALID_N 12XX_1_LVDS_VALID_P 12XX_1_MCU_CLKOUT 12XX_1_MCU_CLKOUT_CONN 12XX_1_MSS_LOGGER 12XX_1_NERROR_IN 12XX_1_NERROR_OUT 12XX_1_NRST 12XX_1_NRST_HOST 12XX_1_NRST_HOST_GS 12XX_1_NRST_LED 12XX_1_NRST_LED_PW 12XX_1_NRST_RS 12XX_1_OSC_CLKOUT 12XX_1_OSC_CLKOUT_CONN 12XX_1_PMIC_CLKOUT 12XX_1_SOP0_TDO 12XX_1_SOP1_SYNCOUT 12XX_1_SOP2_PMICCLKOUT 12XX_1_SPI_CLK1 12XX_1_SPI_CS1 12XX_1_SPI_HOST_INTR1 12XX_1_SPI_MISO1 12XX_1_SPI_MOSI1 12XX_1_TCK 12XX_1_TDI 12XX_1_TDO 12XX_1_TMS 12XX_1_UART_RX 12XX_1_UART_TX 12XX_1_WARM_RST 12XX_1_XTAL_CLKM 12XX_1_XTAL_CLKP 12XX_1_XTALP_RS 12XX_2_BSS_LOGGER 12XX_2_CSI2_CLK_N 12XX_2_CSI2_CLK_P 12XX_2_CSI2_TX0_N 12XX_2_CSI2_TX0_P 12XX_2_CSI2_TX1_N 12XX_2_CSI2_TX1_P 12XX_2_CSI2_TX2_N 12XX_2_CSI2_TX2_P 12XX_2_CSI2_TX3_N 12XX_2_CSI2_TX3_P 12XX_2_DIG_SYNCIN 12XX_2_DIG_SYNCIN_RS 12XX_2_DIG_SYNCOUT 12XX_2_FMCW_CLKOUT 12XX_2_FMCW_SYNCOUT 12XX_2_GPIO_0 12XX_2_GPIO_1 12XX_2_GPIO_2 12XX_2_LVDS_FRCLK_N 12XX_2_LVDS_FRCLK_P 12XX_2_LVDS_VALID_N 12XX_2_LVDS_VALID_P 12XX_2_MCU_CLKOUT 12XX_2_MSS_LOGGER 12XX_2_NERROR_IN 12XX_2_NERROR_OUT 12XX_2_NRST 12XX_2_NRST_HOST 12XX_2_NRST_HOST_GS 12XX_2_NRST_LED 12XX_2_NRST_LED_PW 12XX_2_NRST_RS 12XX_2_OSC_CLKOUT 12XX_2_PMIC_CLKOUT 12XX_2_SOP0_TDO 12XX_2_SOP1_SYNCOUT 12XX_2_SOP2_PMICCLKOUT 12XX_2_SPI_CLK1 12XX_2_SPI_CS1 12XX_2_SPI_HOST_INTR1 12XX_2_SPI_MISO1 12XX_2_SPI_MOSI1 12XX_2_TCK 12XX_2_TDI 12XX_2_TDO 12XX_2_TMS 12XX_2_UART_RX 12XX_2_UART_TX 12XX_2_WARM_RST 12XX_2_XTAL_CLKM 12XX_2_XTAL_CLKP 12XX_3_BSS_LOGGER 12XX_3_CSI2_CLK_N 12XX_3_CSI2_CLK_P 12XX_3_CSI2_TX0_N 12XX_3_CSI2_TX0_P 12XX_3_CSI2_TX1_N 12XX_3_CSI2_TX1_P 12XX_3_CSI2_TX2_N 12XX_3_CSI2_TX2_P 12XX_3_CSI2_TX3_N 12XX_3_CSI2_TX3_P 12XX_3_DIG_SYNCIN 12XX_3_DIG_SYNCIN_RS 12XX_3_DIG_SYNCOUT 12XX_3_FMCW_CLKOUT 12XX_3_FMCW_SYNCOUT 12XX_3_GPIO_0 12XX_3_GPIO_1 12XX_3_GPIO_2 12XX_3_LVDS_FRCLK_N 12XX_3_LVDS_FRCLK_P 12XX_3_LVDS_VALID_N 12XX_3_LVDS_VALID_P 12XX_3_MCU_CLKOUT 12XX_3_MSS_LOGGER 12XX_3_NERROR_IN 12XX_3_NERROR_OUT 12XX_3_NRST 12XX_3_NRST_HOST 12XX_3_NRST_HOST_GS 12XX_3_NRST_LED 12XX_3_NRST_LED_PW 12XX_3_NRST_RS 12XX_3_OSC_CLKOUT 12XX_3_OSC_CLKOUT_CONN 12XX_3_PMIC_CLKOUT 12XX_3_SOP0_TDO 12XX_3_SOP1_SYNCOUT 12XX_3_SOP2_PMICCLKOUT 12XX_3_SPI_CLK1 12XX_3_SPI_CS1 12XX_3_SPI_HOST_INTR1 12XX_3_SPI_MISO1 12XX_3_SPI_MOSI1 12XX_3_TCK 12XX_3_TDI 12XX_3_TDO 12XX_3_TMS 12XX_3_UART_RX 12XX_3_UART_TX 12XX_3_WARM_RST 12XX_3_XTAL_CLKM 12XX_3_XTAL_CLKP 12XX_3_XTALP_RS 12XX_4_BSS_LOGGER 12XX_4_CSI2_CLK_N 12XX_4_CSI2_CLK_P 12XX_4_CSI2_TX0_N 12XX_4_CSI2_TX0_P 12XX_4_CSI2_TX1_N 12XX_4_CSI2_TX1_P 12XX_4_CSI2_TX2_N 12XX_4_CSI2_TX2_P 12XX_4_CSI2_TX3_N 12XX_4_CSI2_TX3_P 12XX_4_DIG_SYNCIN 12XX_4_DIG_SYNCIN_RS 12XX_4_DIG_SYNCOUT 12XX_4_FMCW_CLKOUT 12XX_4_FMCW_SYNCOUT 12XX_4_GPIO_0 12XX_4_GPIO_1 12XX_4_GPIO_2 12XX_4_LVDS_FRCLK_N 12XX_4_LVDS_FRCLK_P 12XX_4_LVDS_VALID_N 12XX_4_LVDS_VALID_P 12XX_4_MCU_CLKOUT 12XX_4_MSS_LOGGER 12XX_4_NERROR_IN 12XX_4_NERROR_OUT 12XX_4_NRST 12XX_4_NRST_HOST 12XX_4_NRST_HOST_GS 12XX_4_NRST_LED 12XX_4_NRST_LED_PW 12XX_4_NRST_RS 12XX_4_OSC_CLKOUT 12XX_4_PMIC_CLKOUT 12XX_4_SOP0_TDO 12XX_4_SOP1_SYNCOUT 12XX_4_SOP2_PMICCLKOUT 12XX_4_SPI_CLK1 12XX_4_SPI_CS1 12XX_4_SPI_HOST_INTR1 12XX_4_SPI_MISO1 12XX_4_SPI_MOSI1 12XX_4_TCK 12XX_4_TDI 12XX_4_TDO 12XX_4_TMS 12XX_4_UART_RX 12XX_4_UART_TX 12XX_4_WARM_RST 12XX_4_XTAL_CLKM 12XX_4_XTAL_CLKP 12XX_RX1_1 12XX_RX1_2 12XX_RX1_3 12XX_RX1_4 12XX_RX2_1 12XX_RX2_2 12XX_RX2_3 12XX_RX2_4 12XX_RX3_1 12XX_RX3_2 12XX_RX3_3 12XX_RX3_4 12XX_RX4_1 12XX_RX4_2 12XX_RX4_3 12XX_RX4_4 12XX_TX1_1 12XX_TX1_2 12XX_TX1_3 12XX_TX1_4 12XX_TX2_1 12XX_TX2_2 12XX_TX2_3 12XX_TX2_4 12XX_TX3_1 12XX_TX3_2 12XX_TX3_3 12XX_TX3_4 40M_BUF_IN_PRIMARY 40M_BUF_IN_SECONDARY AR_1V4_SYNTH_1 AR_1V4_SYNTH_2 AR_1V4_SYNTH_3 AR_1V4_SYNTH_4 BSS_LOGGER_RS_1 BSS_LOGGER_RS_2 BSS_LOGGER_RS_3 BSS_LOGGER_RS_4 BUF_CLKOUT1 BUF_CLKOUT1_RS BUF_CLKOUT2_RS BUF_CLKOUT3 BUF_CLKOUT3_RS BUF_CLKOUT4_RS CONN_MONITOR_1 CONN_MONITOR_2 DIG_SYNC_SOURCE DIG_SYNCOUT_RS_1 DIG_SYNCOUT_RS_2 DIG_SYNCOUT_RS_3 DIG_SYNCOUT_RS_4 EXT_40M_BUF_12XX_1_RS EXT_40MHZ_CLK_1V8 EXT_DIG_SYNC GPADC1_1 GPADC1_2 GPADC1_3 GPADC1_4 GPADC1_CONN_1 GPADC1_CONN_2 GPADC1_CONN_3 GPADC1_CONN_4 GPADC2_1 GPADC2_2 GPADC2_3 GPADC2_4 GPADC2_CONN_1 GPADC2_CONN_2 GPADC2_CONN_3 GPADC2_CONN_4 GPADC3_1 GPADC3_2 GPADC3_3 GPADC3_4 GPADC3_CONN_1 GPADC3_CONN_2 GPADC3_CONN_3 GPADC3_CONN_4 GPADC4_1 GPADC4_2 GPADC4_3 GPADC4_4 GPADC4_CONN_1 GPADC4_CONN_2 GPADC4_CONN_3 GPADC4_CONN_4 GPADC5_1 GPADC5_2 GPADC5_3 GPADC5_4 GPADC5_CONN_1 GPADC5_CONN_2 GPADC5_CONN_3 GPADC5_CONN_4 GPADC6_1 GPADC6_2 GPADC6_3 GPADC6_4 GPADC6_CONN_1 GPADC6_CONN_2 GPADC6_CONN_3 GPADC6_CONN_4 LMK1_CLK_EN LMK1_CLK_SEL LMK1_nCLK LMK1_OE LMK2_CLK_EN LMK2_CLK_EN_N LMK2_CLK_EN_P LMK2_CLK_SEL LMK2_OE MCU_CLKOUT_RS_1 MCU_CLKOUT_RS_2 MCU_CLKOUT_RS_3 MCU_CLKOUT_RS_4 MSS_LOGGER_RS_1 MSS_LOGGER_RS_2 MSS_LOGGER_RS_3 MSS_LOGGER_RS_4 NERROR_OUT NERROR_OUT_LED NERROR_OUT_RS_1 NERROR_OUT_RS_2 NERROR_OUT_RS_3 NERROR_OUT_RS_4 NetDS4_2 NetDS5_2 NetDS6_2 NetDS7_2 OSC_CLKOUT_RS_1 OSC_CLKOUT_RS_2 OSC_CLKOUT_RS_3 OSC_CLKOUT_RS_4 PMIC1_GPIO2 PMIC1_GPIO3 PMIC1_SCL PMIC1_SDA PMIC2_GPIO2 PMIC2_GPIO3 PMIC2_TMPSNS_SCL PMIC2_TMPSNS_SDA PMIC_BUCK_EN PMIC_BUCKEN_CONN PMIC_CLKOUT_RS_1 PMIC_CLKOUT_RS_2 PMIC_CLKOUT_RS_3 PMIC_CLKOUT_RS_4 PMIC_NRST PMIC_NRST_CONN QSPI_CLK_1 QSPI_CLK_2 QSPI_CLK_3 QSPI_CLK_4 QSPI_CLK_RS_1 QSPI_CLK_RS_2 QSPI_CLK_RS_3 QSPI_CLK_RS_4 QSPI_CS_1 QSPI_CS_2 QSPI_CS_3 QSPI_CS_4 QSPI_CS_RS_1 QSPI_CS_RS_2 QSPI_CS_RS_3 QSPI_CS_RS_4 QSPI_D0_1 QSPI_D0_2 QSPI_D0_3 QSPI_D0_4 QSPI_D0_RS_1 QSPI_D0_RS_2 QSPI_D0_RS_3 QSPI_D0_RS_4 QSPI_D1_1 QSPI_D1_2 QSPI_D1_3 QSPI_D1_4 QSPI_D1_RS_1 QSPI_D1_RS_2 QSPI_D1_RS_3 QSPI_D1_RS_4 QSPI_D2_1 QSPI_D2_2 QSPI_D2_3 QSPI_D2_4 QSPI_D2_RS_1 QSPI_D2_RS_2 QSPI_D2_RS_3 QSPI_D2_RS_4 QSPI_D3_1 QSPI_D3_2 QSPI_D3_3 QSPI_D3_4 QSPI_D3_RS_1 QSPI_D3_RS_2 QSPI_D3_RS_3 QSPI_D3_RS_4 SPI_HOST_INTR1_RS_1 SPI_HOST_INTR1_RS_2 SPI_HOST_INTR1_RS_3 SPI_HOST_INTR1_RS_4 SPI_MISO1_RS_1 SPI_MISO1_RS_2 SPI_MISO1_RS_3 SPI_MISO1_RS_4 TDO_RS_1 TDO_RS_2 TDO_RS_3 TDO_RS_4 TMP1_ADD0 TMP2_ADD0 TMP_ALERT TMPSNS_ALERT TMPSNS_SCL TMPSNS_SDA UART_TX_RS_1 UART_TX_RS_2 UART_TX_RS_3 UART_TX_RS_4 XWR_CONN_TP1 XWR_CONN_TP2 XWR_CONN_TP3 XWR_CONN_TP4
net class SYSTEM_5V: SYSTEM_5V0
net class SYSTEM_5V_INPUT: PMIC1_VANA PMIC1_VIN_B0 PMIC1_VIN_B1 PMIC1_VIN_B2 PMIC1_VIN_B3 PMIC2_VANA PMIC2_VIN_B0 PMIC2_VIN_B1 PMIC2_VIN_B2 PMIC2_VIN_B3
net class SYSTEM_3V3: LMK1_3V3 LMK2_3V3 QSPI_FLASH_3V3_1 QSPI_FLASH_3V3_2 QSPI_FLASH_3V3_3 QSPI_FLASH_3V3_4 SYSTEM_3V3 TMP1_3V3 TMP2_3V3
net class SYSTEM_1V8: LMK1_1V8 SYSTEM_1V8
net class PMIC_OUTPUT: PMIC1_FB_B0 PMIC1_FB_B1 PMIC1_FB_B2 PMIC1_FB_B3 PMIC1_SW_B0 PMIC1_SW_B1 PMIC1_SW_B2 PMIC1_SW_B3 PMIC2_FB_B0 PMIC2_FB_B1 PMIC2_FB_B2 PMIC2_FB_B3 PMIC2_SW_B0 PMIC2_SW_B1 PMIC2_SW_B2 PMIC2_SW_B3
net class PMIC_CONTROL: 12XX_1_PMIC_CLKOUT 12XX_3_PMIC_CLKOUT PMIC1_GPIO2 PMIC1_GPIO3 PMIC1_INTN PMIC1_PGOOD_RS PMIC1_SCL PMIC1_SDA PMIC2_GPIO2 PMIC2_GPIO3 PMIC2_INTN PMIC2_PGOOD_RS PMIC2_TMPSNS_SCL PMIC2_TMPSNS_SDA PMIC_BUCK_EN PMIC_NRST
net class 12XX_QSPI: QSPI_CLK_1 QSPI_CLK_2 QSPI_CLK_3 QSPI_CLK_4 QSPI_CLK_RS_1 QSPI_CLK_RS_2 QSPI_CLK_RS_3 QSPI_CLK_RS_4 QSPI_CS_1 QSPI_CS_2 QSPI_CS_3 QSPI_CS_4 QSPI_CS_RS_1 QSPI_CS_RS_2 QSPI_CS_RS_3 QSPI_CS_RS_4 QSPI_D0_1 QSPI_D0_2 QSPI_D0_3 QSPI_D0_4 QSPI_D1_1 QSPI_D1_2 QSPI_D1_3 QSPI_D1_4 QSPI_D2_1 QSPI_D2_2 QSPI_D2_3 QSPI_D2_4 QSPI_D3_1 QSPI_D3_2 QSPI_D3_3 QSPI_D3_4
net class 12XX_POWER_ANA: AR_1V4_APLL_1 AR_1V4_APLL_2 AR_1V4_APLL_3 AR_1V4_APLL_4 AR_1V4_SYNTH_1 AR_1V4_SYNTH_2 AR_1V4_SYNTH_3 AR_1V4_SYNTH_4 AR_VBGAP_1 AR_VBGAP_2 AR_VBGAP_3 AR_VBGAP_4 AR_VOUT_PA_1 AR_VOUT_PA_2 AR_VOUT_PA_3 AR_VOUT_PA_4
net class 12XX_GENERAL: 12XX_1_BSS_LOGGER 12XX_1_GPIO_0 12XX_1_GPIO_1 12XX_1_GPIO_2 12XX_1_MSS_LOGGER 12XX_1_NERROR_IN 12XX_1_NERROR_OUT 12XX_1_NRST 12XX_1_SCL 12XX_1_SDA 12XX_1_SPI_CLK1 12XX_1_SPI_CS1 12XX_1_SPI_HOST_INTR1 12XX_1_SPI_MISO1 12XX_1_SPI_MOSI1 12XX_1_UART_RX 12XX_1_UART_TX 12XX_1_WARM_RST 12XX_2_BSS_LOGGER 12XX_2_GPIO_0 12XX_2_GPIO_1 12XX_2_GPIO_2 12XX_2_MSS_LOGGER 12XX_2_NERROR_IN 12XX_2_NERROR_OUT 12XX_2_NRST 12XX_2_SCL 12XX_2_SDA 12XX_2_SPI_CLK1 12XX_2_SPI_CS1 12XX_2_SPI_HOST_INTR1 12XX_2_SPI_MISO1 12XX_2_SPI_MOSI1 12XX_2_UART_RX 12XX_2_UART_TX 12XX_2_WARM_RST 12XX_3_BSS_LOGGER 12XX_3_GPIO_0 12XX_3_GPIO_1 12XX_3_GPIO_2 12XX_3_MSS_LOGGER 12XX_3_NERROR_IN 12XX_3_NERROR_OUT 12XX_3_NRST 12XX_3_SCL 12XX_3_SDA 12XX_3_SPI_CLK1 12XX_3_SPI_CS1 12XX_3_SPI_HOST_INTR1 12XX_3_SPI_MISO1 12XX_3_SPI_MOSI1 12XX_3_UART_RX 12XX_3_UART_TX 12XX_3_WARM_RST 12XX_4_BSS_LOGGER 12XX_4_GPIO_0 12XX_4_GPIO_1 12XX_4_GPIO_2 12XX_4_MSS_LOGGER 12XX_4_NERROR_IN 12XX_4_NERROR_OUT 12XX_4_NRST 12XX_4_SCL 12XX_4_SDA 12XX_4_SPI_CLK1 12XX_4_SPI_CS1 12XX_4_SPI_HOST_INTR1 12XX_4_SPI_MISO1 12XX_4_SPI_MOSI1 12XX_4_UART_RX 12XX_4_UART_TX 12XX_4_WARM_RST BSS_LOGGER_RS_1 BSS_LOGGER_RS_2 BSS_LOGGER_RS_3 BSS_LOGGER_RS_4 MSS_LOGGER_RS_1 MSS_LOGGER_RS_2 MSS_LOGGER_RS_3 MSS_LOGGER_RS_4 NERROR_OUT_RS_1 NERROR_OUT_RS_2 NERROR_OUT_RS_3 NERROR_OUT_RS_4 SDA_RS_1 SDA_RS_2 SDA_RS_3 SDA_RS_4 SPI_HOST_INTR1_RS_1 SPI_HOST_INTR1_RS_2 SPI_HOST_INTR1_RS_3 SPI_HOST_INTR1_RS_4 SPI_MISO1_RS_1 SPI_MISO1_RS_2 SPI_MISO1_RS_3 SPI_MISO1_RS_4 UART_TX_RS_1 UART_TX_RS_2 UART_TX_RS_3 UART_TX_RS_4
net class 12XX_DEBUG: GPADC1_1 GPADC1_2 GPADC1_3 GPADC1_4 GPADC1_CONN_1 GPADC1_CONN_2 GPADC1_CONN_3 GPADC1_CONN_4 GPADC2_1 GPADC2_2 GPADC2_3 GPADC2_4 GPADC2_CONN_1 GPADC2_CONN_2 GPADC2_CONN_3 GPADC2_CONN_4 GPADC3_1 GPADC3_2 GPADC3_3 GPADC3_4 GPADC3_CONN_1 GPADC3_CONN_2 GPADC3_CONN_3 GPADC3_CONN_4 GPADC4_1 GPADC4_2 GPADC4_3 GPADC4_4 GPADC4_CONN_1 GPADC4_CONN_2 GPADC4_CONN_3 GPADC4_CONN_4 GPADC5_1 GPADC5_2 GPADC5_3 GPADC5_4 GPADC5_CONN_1 GPADC5_CONN_2 GPADC5_CONN_3 GPADC5_CONN_4 GPADC6_1 GPADC6_2 GPADC6_3 GPADC6_4 GPADC6_CONN_1 GPADC6_CONN_2 GPADC6_CONN_3 GPADC6_CONN_4
net class 12XX_ANTENNA: 12XX_RX1_1 12XX_RX1_2 12XX_RX1_3 12XX_RX1_4 12XX_RX2_1 12XX_RX2_2 12XX_RX2_3 12XX_RX2_4 12XX_RX3_1 12XX_RX3_2 12XX_RX3_3 12XX_RX3_4 12XX_RX4_1 12XX_RX4_2 12XX_RX4_3 12XX_RX4_4 12XX_TX1_1 12XX_TX1_2 12XX_TX1_3 12XX_TX1_4 12XX_TX2_1 12XX_TX2_2 12XX_TX2_3 12XX_TX2_4 12XX_TX3_1 12XX_TX3_2 12XX_TX3_3 12XX_TX3_4
net class XWR23_POWER_1V8: PMIC2_12XX_23_1V8
net class XWR23_POWER_1V2: PMIC2_12XX_23_1V2
net class XWR14_POWER_1V8: PMIC1_12XX_14_1V8
net class XWR14_POWER_1V2: PMIC1_12XX_14_1V2
net class XWR4_POWER_RF: PMIC1_12XX_4_1V0
net class XWR3_POWER_RF: PMIC2_12XX_3_1V0
net class XWR2_POWER_RF: PMIC2_12XX_2_1V0
net class 12XX_2_POWER_1V0_RF: 12XX_2_1V0_RF1_FILT 12XX_2_1V0_RF2_FILT
net class XWR1_POWER_RF: PMIC1_12XX_1_1V0
net class 12XX_SAFETY: NERROR_OUT TMPSNS_ALERT
net class 12XX_3_CSI_LVDS: 12XX_3_CSI2_CLK_N 12XX_3_CSI2_CLK_P 12XX_3_CSI2_TX0_N 12XX_3_CSI2_TX0_P 12XX_3_CSI2_TX1_N 12XX_3_CSI2_TX1_P 12XX_3_CSI2_TX2_N 12XX_3_CSI2_TX2_P 12XX_3_CSI2_TX3_N 12XX_3_CSI2_TX3_P 12XX_3_LVDS_FRCLK_N 12XX_3_LVDS_FRCLK_P 12XX_3_LVDS_VALID_N 12XX_3_LVDS_VALID_P
net class 12XX_3_SOP_RESET: 12XX_3_NRST_HOST 12XX_3_SOP0_TDO 12XX_3_SOP1_SYNCOUT 12XX_3_SOP2_PMICCLKOUT 12XX_3_WARM_RST
net class 12XX_2_JTAG: 12XX_2_TCK 12XX_2_TDI 12XX_2_TDO 12XX_2_TMS
net class 12XX_3_GENERAL: 12XX_3_BSS_LOGGER 12XX_3_GPIO_0 12XX_3_GPIO_1 12XX_3_GPIO_2 12XX_3_MSS_LOGGER 12XX_3_SPI_CLK1 12XX_3_SPI_CS1 12XX_3_SPI_HOST_INTR1 12XX_3_SPI_MISO1 12XX_3_SPI_MOSI1 12XX_3_UART_RX 12XX_3_UART_TX
net class 12XX_2_CSI_LVDS: 12XX_2_CSI2_CLK_N 12XX_2_CSI2_CLK_P 12XX_2_CSI2_TX0_N 12XX_2_CSI2_TX0_P 12XX_2_CSI2_TX1_N 12XX_2_CSI2_TX1_P 12XX_2_CSI2_TX2_N 12XX_2_CSI2_TX2_P 12XX_2_CSI2_TX3_N 12XX_2_CSI2_TX3_P 12XX_2_LVDS_FRCLK_N 12XX_2_LVDS_FRCLK_P 12XX_2_LVDS_VALID_N 12XX_2_LVDS_VALID_P
net class 12XX_3_JTAG: 12XX_3_TCK 12XX_3_TDI 12XX_3_TDO 12XX_3_TMS
net class 12XX_4_CSI_LVDS: 12XX_4_CSI2_CLK_N 12XX_4_CSI2_CLK_P 12XX_4_CSI2_TX0_N 12XX_4_CSI2_TX0_P 12XX_4_CSI2_TX1_N 12XX_4_CSI2_TX1_P 12XX_4_CSI2_TX2_N 12XX_4_CSI2_TX2_P 12XX_4_CSI2_TX3_N 12XX_4_CSI2_TX3_P 12XX_4_LVDS_FRCLK_N 12XX_4_LVDS_FRCLK_P 12XX_4_LVDS_VALID_N 12XX_4_LVDS_VALID_P
net class 12XX_1_SOP_RESET: 12XX_1_NRST_HOST 12XX_1_SOP0_TDO 12XX_1_SOP1_SYNCOUT 12XX_1_SOP2_PMICCLKOUT 12XX_1_WARM_RST
net class 12XX_1_JTAG: 12XX_1_TCK 12XX_1_TDI 12XX_1_TDO 12XX_1_TMS
net class 12XX_1_GENERAL: 12XX_1_BSS_LOGGER 12XX_1_GPIO_0 12XX_1_GPIO_1 12XX_1_GPIO_2 12XX_1_MSS_LOGGER 12XX_1_SPI_CLK1 12XX_1_SPI_CS1 12XX_1_SPI_HOST_INTR1 12XX_1_SPI_MISO1 12XX_1_SPI_MOSI1 12XX_1_UART_RX 12XX_1_UART_TX
net class 12XX_1_CSI_LVDS: 12XX_1_CSI2_CLK_N 12XX_1_CSI2_CLK_P 12XX_1_CSI2_TX0_N 12XX_1_CSI2_TX0_P 12XX_1_CSI2_TX1_N 12XX_1_CSI2_TX1_P 12XX_1_CSI2_TX2_N 12XX_1_CSI2_TX2_P 12XX_1_CSI2_TX3_N 12XX_1_CSI2_TX3_P 12XX_1_LVDS_FRCLK_N 12XX_1_LVDS_FRCLK_P 12XX_1_LVDS_VALID_N 12XX_1_LVDS_VALID_P
component class SYSTEM_POWER: C94 C149 C162 C163 C164 C165 C205 C206 R37 R38 R53 R61 R62 R77 R86 R87 R88 R89 R90 R91 R92 R93 R189 R190 R191 R204 R205 R206 R207 R208 R209 R210 R211 R212 U6 U11 U12 U13
component class SYSTEM_LED_INDICATORS: DS1 DS2 DS3 DS4 DS5 DS6 DS7 Q1 Q2 Q3 Q4 Q5 R192 R193 R194 R195 R196 R197 R198 R199 R200 R201 R202 R203
component class SYSTEM_3V3_SUPPLY: C9 C202 C203 U5
component class HOST_CONNECTORS: C190 C191 C192 C193 C194 J4 J5 J6 R19 R20 R98 R99 R100 R101 R102 R112 R114 R125 R145 R146 R147 R148 R149 R150 R151 R152 R153 R154 R155 R156 R157 R158 R159 R160 R161 R162 R163 TP8 TP12 TP13 TP15 TP16 TP17 TP18 TP19 TP20 TP25 TP29 TP30 TP32 TP33
component class Header: J1_1 J1_2 J1_3 J1_4 J2
component class DIG_SYNC_LO_20GHZ: C181 C182 C183 C184 C185 C186 C187 C188 C189 L35 R132 R133 R134 R135 R136 R137 R138 R139 R140 R141 R142 R143 R144 U8
component class SYSTEM_TEST_CONN_TERMINATION: J2 J3 R79 R82 R83 R84 R85 R186 R187
component class 40MHZ_CLOCK: C167 C168 C169 C170 C171 C172 C173 C174 C175 C176 C177 C178 C179 C180 L33 L34 R103 R104 R105 R106 R107 R108 R109 R110 R111 R113 R115 R116 R117 R118 R119 R120 R121 R122 R123 R124 R126 R127 R128 R129 R130 R131 R213 R214 U7 Y1 Y2
component class 12XX_4: C1_4 C2_4 C3_4 C4_4 C5_4 C6_4 C7_4 C8_4 J1_4 R1_4 R2_4 R3_4 R4_4 R5_4 R6_4 R7_4 R8_4 R9_4 R10_4 R11_4 R12_4 R13_4 R14_4 R15_4 R16_4 R17_4 R18_4 R21_4 R22_4 R23_4 R24_4 R25_4 R26_4 R27_4 R28_4 R29_4 R30_4 R31_4 R32_4 R33_4 R188_4 TP1_4 TP2_4 TP3_4 U1_4 U2_4
component class 12XX_3: C1_3 C2_3 C3_3 C4_3 C5_3 C6_3 C7_3 C8_3 J1_3 R1_3 R2_3 R3_3 R4_3 R5_3 R6_3 R7_3 R8_3 R9_3 R10_3 R11_3 R12_3 R13_3 R14_3 R15_3 R16_3 R17_3 R18_3 R21_3 R22_3 R23_3 R24_3 R25_3 R26_3 R27_3 R28_3 R29_3 R30_3 R31_3 R32_3 R33_3 R188_3 TP1_3 TP2_3 TP3_3 U1_3 U2_3
component class 12XX_2: C1_2 C2_2 C3_2 C4_2 C5_2 C6_2 C7_2 C8_2 J1_2 R1_2 R2_2 R3_2 R4_2 R5_2 R6_2 R7_2 R8_2 R9_2 R10_2 R11_2 R12_2 R13_2 R14_2 R15_2 R16_2 R17_2 R18_2 R21_2 R22_2 R23_2 R24_2 R25_2 R26_2 R27_2 R28_2 R29_2 R30_2 R31_2 R32_2 R33_2 R188_2 TP1_2 TP2_2 TP3_2 U1_2 U2_2
component class 12XX_2_12XX_3_LP87524P: C95 C96 C97 C98 C99 C100 C101 C102 C103 C104 C105 C106 C107 C108 C109 C110 C111 C112 C113 C114 C115 C116 C117 C118 C119 C120 C121 C122 C123 C124 C125 C126 C127 L25 L26 L27 L28 L29 L30 L31 L32 R59 R60 R63 R64 R65 R66 R67 R68 R69 R70 R71 R72 R74 R75 R76 R78 R80 R81 R95 R97 TP21 TP22 TP23 TP24 TP26 TP27 TP28 TP31 U4
component class 12XX_2_12XX_3_LC_Filtering: C70 C71 C72 C73 C74 C75 C76 C77 C79 C80 C82 C83 C84 C85 C87 C88 C90 C91 C92 C93 C153 C154 C155 C156 C157 C158 C159 C160 C166 C201 C204 C207 L17 L18 L19 L20 L21 L22 L23 L24
component class 12XX_1: C1_1 C2_1 C3_1 C4_1 C5_1 C6_1 C7_1 C8_1 J1_1 R1_1 R2_1 R3_1 R4_1 R5_1 R6_1 R7_1 R8_1 R9_1 R10_1 R11_1 R12_1 R13_1 R14_1 R15_1 R16_1 R17_1 R18_1 R21_1 R22_1 R23_1 R24_1 R25_1 R26_1 R27_1 R28_1 R29_1 R30_1 R31_1 R32_1 R33_1 R188_1 TP1_1 TP2_1 TP3_1 U1_1 U2_1
component class 12XX_1_12XX_4_LP87524P: C37 C38 C39 C40 C41 C42 C43 C44 C45 C46 C47 C48 C49 C50 C51 C52 C53 C54 C55 C56 C57 C58 C59 C60 C61 C62 C63 C64 C65 C66 C67 C68 C69 L9 L10 L11 L12 L13 L14 L15 L16 R34 R36 R39 R40 R41 R42 R43 R44 R45 R46 R47 R48 R49 R50 R51 R52 R54 R55 R56 R57 R58 R73 R94 R96 TP4 TP5 TP6 TP7 TP9 TP10 TP11 TP14 U3
component class 12XX_1_12XX_4_LC_Filtering: C10 C11 C12 C13 C14 C15 C16 C17 C18 C19 C20 C21 C22 C23 C24 C25 C26 C27 C28 C29 C30 C31 C32 C33 C34 C35 C36 C78 C81 C86 C89 C150 C151 C152 C161 L1 L2 L3 L4 L5 L6 L7 L8 R35
component class AssemblyNote: ZZ1 ZZ2 ZZ3 ZZ4
component class FiducialMark: FID1 FID2 FID3 FID4 FID5 FID6
component class EVM_HARDWARE: FID1 FID2 FID3 FID4 FID5 FID6 Logo1 Logo2 Logo3 Logo4 Logo5 LOGO6 ZZ1 ZZ2 ZZ3 ZZ4
component class Logo: Logo2
net class 12XX_1_POWER_1V0_RF: 12XX_1_1V0_RF1_FILT 12XX_1_1V0_RF2_FILT
net class 12XX_1_POWER_1V2: 12XX_1_1V2_FILT
net class 12XX_1_POWER_1V8: 12XX_1_1V8_FILT
net class 12XX_2_POWER_1V2: 12XX_2_1V2_FILT
net class 12XX_3_POWER_1V2: 12XX_3_1V2_FILT
net class 12XX_3_POWER_1V8: 12XX_2_1V8_FILT 12XX_3_1V8_FILT
net class 12XX_3_POWER_RF: 12XX_3_1V0_RF1_FILT 12XX_3_1V0_RF2_FILT
net class 12XX_4_POWER_1V2: 12XX_4_1V2_FILT
net class 12XX_4_POWER_1V8: 12XX_4_1V8_FILT
net class 12XX_4_POWER_RF: 12XX_4_1V0_RF1_FILT 12XX_4_1V0_RF2_FILT
net class XWR_20GHZ_LO: 12XX_1_FMCW_CLKOUT 12XX_1_FMCW_SYNCOUT 12XX_2_FMCW_CLKOUT 12XX_2_FMCW_SYNCOUT 12XX_3_FMCW_CLKOUT 12XX_3_FMCW_SYNCOUT 12XX_4_FMCW_CLKOUT 12XX_4_FMCW_SYNCOUT
component class SYSTEM_TEMP_SENSORS: C195 C196 C197 C198 C199 C200 R164 R165 R166 R167 R168 R169 R170 R171 R172 R173 U9 U10
net class Antenna: 12XX_1_FMCW_CLKOUT 12XX_1_FMCW_SYNCOUT 12XX_2_FMCW_CLKOUT 12XX_2_FMCW_SYNCOUT 12XX_3_FMCW_CLKOUT 12XX_3_FMCW_SYNCOUT 12XX_4_FMCW_CLKOUT 12XX_4_FMCW_SYNCOUT 12XX_RX1_1 12XX_RX1_2 12XX_RX1_3 12XX_RX1_4 12XX_RX2_1 12XX_RX2_2 12XX_RX2_3 12XX_RX2_4 12XX_RX3_1 12XX_RX3_2 12XX_RX3_3 12XX_RX3_4 12XX_RX4_1 12XX_RX4_2 12XX_RX4_3 12XX_RX4_4 12XX_TX1_1 12XX_TX1_2 12XX_TX1_3 12XX_TX1_4 12XX_TX2_1 12XX_TX2_2 12XX_TX2_3 12XX_TX2_4 12XX_TX3_1 12XX_TX3_2 12XX_TX3_3 12XX_TX3_4
net class 12XX2_SOP_RESET: 12XX_2_NRST_HOST 12XX_2_SOP0_TDO 12XX_2_SOP1_SYNCOUT 12XX_2_SOP2_PMICCLKOUT 12XX_2_WARM_RST
net class 12XX_2_GENERAL: 12XX_2_BSS_LOGGER 12XX_2_GPIO_0 12XX_2_GPIO_1 12XX_2_GPIO_2 12XX_2_MSS_LOGGER 12XX_2_SPI_CLK1 12XX_2_SPI_CS1 12XX_2_SPI_HOST_INTR1 12XX_2_SPI_MISO1 12XX_2_SPI_MOSI1 12XX_2_UART_RX 12XX_2_UART_TX
net class 12XX_4_GENERAL: 12XX_4_BSS_LOGGER 12XX_4_GPIO_0 12XX_4_GPIO_1 12XX_4_GPIO_2 12XX_4_MSS_LOGGER 12XX_4_SPI_CLK1 12XX_4_SPI_CS1 12XX_4_SPI_HOST_INTR1 12XX_4_SPI_MISO1 12XX_4_SPI_MOSI1 12XX_4_UART_RX 12XX_4_UART_TX
net class 12XX_4_JTAG: 12XX_4_TCK 12XX_4_TDI 12XX_4_TDO 12XX_4_TMS
net class 12XX_4_SOP_RESET: 12XX_4_NRST_HOST 12XX_4_SOP0_TDO 12XX_4_SOP1_SYNCOUT 12XX_4_SOP2_PMICCLKOUT 12XX_4_WARM_RST
net class "LC Power": 12XX_1_1V0_RF1_FILT 12XX_1_1V0_RF2_FILT 12XX_1_1V2_FILT 12XX_1_1V8_FILT 12XX_2_1V0_RF1_FILT 12XX_2_1V0_RF2_FILT 12XX_2_1V2_FILT 12XX_2_1V8_FILT 12XX_3_1V0_RF1_FILT 12XX_3_1V0_RF2_FILT 12XX_3_1V2_FILT 12XX_3_1V8_FILT 12XX_4_1V0_RF1_FILT 12XX_4_1V0_RF2_FILT 12XX_4_1V2_FILT 12XX_4_1V8_FILT
net class 12XX_SYNC: 12XX_1_DIG_SYNCIN 12XX_1_DIG_SYNCIN_RS 12XX_1_DIG_SYNCOUT 12XX_2_DIG_SYNCIN 12XX_2_DIG_SYNCIN_RS 12XX_2_DIG_SYNCOUT 12XX_3_DIG_SYNCIN 12XX_3_DIG_SYNCIN_RS 12XX_3_DIG_SYNCOUT 12XX_4_DIG_SYNCIN 12XX_4_DIG_SYNCIN_RS 12XX_4_DIG_SYNCOUT DIG_SYNC_SOURCE DIG_SYNCOUT_RS_1 DIG_SYNCOUT_RS_2 DIG_SYNCOUT_RS_3 DIG_SYNCOUT_RS_4 EXT_DIG_SYNC
net class 12XX_CLOCK: 12XX_1_MCU_CLKOUT 12XX_1_MCU_CLKOUT_CONN 12XX_1_MCU_CLKOUT_RS 12XX_1_OSC_CLKOUT 12XX_1_OSC_CLKOUT_CONN 12XX_1_PMIC_CLKOUT 12XX_1_XTAL_CLKM 12XX_1_XTAL_CLKP 12XX_1_XTALP_RS 12XX_2_MCU_CLKOUT 12XX_2_OSC_CLKOUT 12XX_2_PMIC_CLKOUT 12XX_2_XTAL_CLKM 12XX_2_XTAL_CLKP 12XX_3_MCU_CLKOUT 12XX_3_OSC_CLKOUT 12XX_3_OSC_CLKOUT_CONN 12XX_3_PMIC_CLKOUT 12XX_3_XTAL_CLKM 12XX_3_XTAL_CLKP 12XX_3_XTALP_RS 12XX_4_MCU_CLKOUT 12XX_4_OSC_CLKOUT 12XX_4_PMIC_CLKOUT 12XX_4_XTAL_CLKM 12XX_4_XTAL_CLKP 40M_BUF_IN_PRIMARY 40M_BUF_IN_SECONDARY BUF_CLKOUT1 BUF_CLKOUT1_RS BUF_CLKOUT2_RS BUF_CLKOUT3 BUF_CLKOUT3_RS BUF_CLKOUT4_RS EXT_40M_BUF_12XX_1_RS EXT_40MHZ_CLK_1V8 MCU_CLKOUT_RS_1 MCU_CLKOUT_RS_2 MCU_CLKOUT_RS_3 MCU_CLKOUT_RS_4 OSC_CLKOUT_RS_1 OSC_CLKOUT_RS_2 OSC_CLKOUT_RS_3 OSC_CLKOUT_RS_4 PMIC_CLKOUT_RS_1 PMIC_CLKOUT_RS_2 PMIC_CLKOUT_RS_3 PMIC_CLKOUT_RS_4
net class 12XX_FMCW_20G: 12XX_1_FMCW_CLKOUT 12XX_1_FMCW_SYNCOUT 12XX_2_FMCW_CLKOUT 12XX_2_FMCW_SYNCOUT 12XX_3_FMCW_CLKOUT 12XX_3_FMCW_SYNCOUT 12XX_4_FMCW_CLKOUT 12XX_4_FMCW_SYNCOUT
net class 12XX_GENERAL: 12XX_1_SPI_CLK1 12XX_1_SPI_CS1 12XX_1_SPI_HOST_INTR1 12XX_1_SPI_MISO1 12XX_1_SPI_MOSI1 12XX_2_SPI_CLK1 12XX_2_SPI_CS1 12XX_2_SPI_HOST_INTR1 12XX_2_SPI_MISO1 12XX_2_SPI_MOSI1 12XX_3_SPI_CLK1 12XX_3_SPI_CS1 12XX_3_SPI_HOST_INTR1 12XX_3_SPI_MISO1 12XX_3_SPI_MOSI1 12XX_4_SPI_CLK1 12XX_4_SPI_CS1 12XX_4_SPI_HOST_INTR1 12XX_4_SPI_MISO1 12XX_4_SPI_MOSI1 SPI_HOST_INTR1_RS_1 SPI_HOST_INTR1_RS_2 SPI_HOST_INTR1_RS_3 SPI_HOST_INTR1_RS_4 SPI_MISO1_RS_1 SPI_MISO1_RS_2 SPI_MISO1_RS_3 SPI_MISO1_RS_4
net class 12XX_JTAG: 12XX_1_TCK 12XX_1_TDI 12XX_1_TDO 12XX_1_TMS 12XX_2_TCK 12XX_2_TDI 12XX_2_TDO 12XX_2_TMS 12XX_3_TCK 12XX_3_TDI 12XX_3_TDO 12XX_3_TMS 12XX_4_TCK 12XX_4_TDI 12XX_4_TDO 12XX_4_TMS TDO_RS_1 TDO_RS_2 TDO_RS_3 TDO_RS_4
net class "Back Drill Nets": 12XX_1_FMCW_CLKOUT 12XX_1_FMCW_SYNCOUT 12XX_3_FMCW_CLKOUT
channel class PROC054C_12XX_1: 12XX_1 12XX_2 12XX_3 12XX_4
channel class PROC054C_12XX_DECOUPLING_CAPS_1: 12XX_1 12XX_2 12XX_3 12XX_4
channel class PROC054C_PULL_UP_DOWN_1: 12XX_1 12XX_2 12XX_3 12XX_4
component class 12XX_4: R174_4 R175_4 R176_4 R177_4 R178_4 R179_4 R180_4 R181_4 R182_4 R183_4 R184_4 R185_4
differential pair 12XX_4_LVDS_VALID: +12XX_4_LVDS_VALID_P -12XX_4_LVDS_VALID_N
differential pair 12XX_4_LVDS_FRCLK: +12XX_4_LVDS_FRCLK_P -12XX_4_LVDS_FRCLK_N
differential pair 12XX_4_CSI2_TX3: +12XX_4_CSI2_TX3_P -12XX_4_CSI2_TX3_N
differential pair 12XX_4_CSI2_TX2: +12XX_4_CSI2_TX2_P -12XX_4_CSI2_TX2_N
differential pair 12XX_4_CSI2_TX1: +12XX_4_CSI2_TX1_P -12XX_4_CSI2_TX1_N
differential pair 12XX_4_CSI2_TX0: +12XX_4_CSI2_TX0_P -12XX_4_CSI2_TX0_N
differential pair 12XX_4_CSI2_CLK: +12XX_4_CSI2_CLK_P -12XX_4_CSI2_CLK_N
differential pair 12XX_3_LVDS_VALID: +12XX_3_LVDS_VALID_P -12XX_3_LVDS_VALID_N
differential pair 12XX_3_LVDS_FRCLK: +12XX_3_LVDS_FRCLK_P -12XX_3_LVDS_FRCLK_N
differential pair 12XX_3_CSI2_TX3: +12XX_3_CSI2_TX3_P -12XX_3_CSI2_TX3_N
differential pair 12XX_3_CSI2_TX2: +12XX_3_CSI2_TX2_P -12XX_3_CSI2_TX2_N
differential pair 12XX_3_CSI2_TX1: +12XX_3_CSI2_TX1_P -12XX_3_CSI2_TX1_N
differential pair 12XX_3_CSI2_TX0: +12XX_3_CSI2_TX0_P -12XX_3_CSI2_TX0_N
differential pair 12XX_3_CSI2_CLK: +12XX_3_CSI2_CLK_P -12XX_3_CSI2_CLK_N
differential pair 12XX_2_LVDS_VALID: +12XX_2_LVDS_VALID_P -12XX_2_LVDS_VALID_N
differential pair 12XX_2_LVDS_FRCLK: +12XX_2_LVDS_FRCLK_P -12XX_2_LVDS_FRCLK_N
differential pair 12XX_2_CSI2_TX3: +12XX_2_CSI2_TX3_P -12XX_2_CSI2_TX3_N
differential pair 12XX_2_CSI2_TX2: +12XX_2_CSI2_TX2_P -12XX_2_CSI2_TX2_N
differential pair 12XX_2_CSI2_TX1: +12XX_2_CSI2_TX1_P -12XX_2_CSI2_TX1_N
differential pair 12XX_2_CSI2_TX0: +12XX_2_CSI2_TX0_P -12XX_2_CSI2_TX0_N
differential pair 12XX_2_CSI2_CLK: +12XX_2_CSI2_CLK_P -12XX_2_CSI2_CLK_N
differential pair 12XX_1_LVDS_VALID: +12XX_1_LVDS_VALID_P -12XX_1_LVDS_VALID_N
differential pair 12XX_1_LVDS_FRCLK: +12XX_1_LVDS_FRCLK_P -12XX_1_LVDS_FRCLK_N
differential pair 12XX_1_CSI2_TX3: +12XX_1_CSI2_TX3_P -12XX_1_CSI2_TX3_N
differential pair 12XX_1_CSI2_TX2: +12XX_1_CSI2_TX2_P -12XX_1_CSI2_TX2_N
differential pair 12XX_1_CSI2_TX1: +12XX_1_CSI2_TX1_P -12XX_1_CSI2_TX1_N
differential pair 12XX_1_CSI2_TX0: +12XX_1_CSI2_TX0_P -12XX_1_CSI2_TX0_N
differential pair 12XX_1_CSI2_CLK: +12XX_1_CSI2_CLK_P -12XX_1_CSI2_CLK_N

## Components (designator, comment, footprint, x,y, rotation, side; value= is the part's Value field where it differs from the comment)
C1_1 "GCM188R71C105KA64D" 0603S 2742.78,2897.55 r90 top locked value=1uF (schematic designator C1)
C1_2 "GCM188R71C105KA64D" 0603S 5073.3,2751.83 r270 top locked value=1uF (schematic designator C1)
C1_3 "GCM188R71C105KA64D" 0603S 4070.8,2905.83 r90 top locked value=1uF (schematic designator C1)
C1_4 "GCM188R71C105KA64D" 0603S 1557.76,2768.38 r0 top locked value=1uF (schematic designator C1)
C2_1 "GCM155R71C224KE02D" 0402S 2563.59,3040.51 r90 bottom locked value=0.22uF (schematic designator C2)
C2_2 "GCM155R71C224KE02D" 0402S 4881.59,2945.09 r90 bottom locked value=0.22uF (schematic designator C2)
C2_3 "GCM155R71C224KE02D" 0402S 3878.59,3040.51 r90 bottom locked value=0.22uF (schematic designator C2)
C2_4 "GCM155R71C224KE02D" 0402S 1393,2941.71 r90 bottom locked value=0.22uF (schematic designator C2)
C3_1 "GCM188R71C105KA64D" 0603S 2696.55,2995.81 r0 top locked value=1uF (schematic designator C3)
C3_2 "GCM188R71C105KA64D" 0603S 5014.55,2901.32 r0 top locked value=1uF (schematic designator C3)
C3_3 "GCM188R71C105KA64D" 0603S 4011.55,2995.81 r0 top locked value=1uF (schematic designator C3)
C3_4 "GCM188R71C105KA64D" 0603S 1526.55,2902.31 r0 top locked value=1uF (schematic designator C3)
C4_1 "GCM155R71C224KE02D" 0402 2720.13,3194 r0 top locked value=0.22uF (schematic designator C4)
C4_2 "GCM155R71C224KE02D" 0402 5014.43,3100.3 r0 top locked value=0.22uF (schematic designator C4)
C4_3 "GCM155R71C224KE02D" 0402 4011.43,3194.3 r0 top locked value=0.22uF (schematic designator C4)
C4_4 "GCM155R71C224KE02D" 0402 1526.43,3112.3 r0 top locked value=0.22uF (schematic designator C4)
C5_1 "GCM21BR71A106KE22L" 0805 2725.58,3288.52 r90 top locked value=10uF (schematic designator C5)
C5_2 "GCM21BR71A106KE22L" 0805 5012.4,3187.53 r90 top locked value=10uF (schematic designator C5)
C5_3 "GCM21BR71A106KE22L" 0805 4008.9,3281.53 r90 top locked value=10uF (schematic designator C5)
C5_4 "GCM21BR71A106KE22L" 0805 1523.9,3214.53 r90 top locked value=10uF (schematic designator C5)
C6_1 "GCM21BR71A106KE22L" 0805L 2148.35,2008.07 r270 bottom locked value=10uF (schematic designator C6)
C6_2 "GCM21BR71A106KE22L" 0805L 4322.67,2007.69 r270 bottom locked value=10uF (schematic designator C6)
C6_3 "GCM21BR71A106KE22L" 0805L 3133.93,3422.47 r90 bottom locked value=10uF (schematic designator C6)
C6_4 "GCM21BR71A106KE22L" 0805L 694.69,3715.83 r180 bottom locked value=10uF (schematic designator C6)
C7_1 "GCM188R71C105KA64D" 0603S 2195.91,2087.69 r0 bottom locked value=1uF (schematic designator C7)
C7_2 "GCM188R71C105KA64D" 0603S 4421.14,2031.28 r0 bottom locked value=1uF (schematic designator C7)
C7_3 "GCM188R71C105KA64D" 0603S 3037.86,3364.87 r180 bottom locked value=1uF (schematic designator C7)
C7_4 "GCM188R71C105KA64D" 0603S 756.26,3626.9 r270 bottom locked value=1uF (schematic designator C7)
C8_1 "CGA2B3X7R1H104K050BB" 0402S 2185.91,2143.45 r0 bottom locked value=0.1uF (schematic designator C8)
C8_2 "CGA2B3X7R1H104K050BB" 0402S 4408.64,2075.26 r0 bottom locked value=0.1uF (schematic designator C8)
C8_3 "CGA2B3X7R1H104K050BB" 0402S 3045.36,3323.4 r180 bottom locked value=0.1uF (schematic designator C8)
C8_4 "CGA2B3X7R1H104K050BB" 0402S 802,3639.4 r270 bottom locked value=0.1uF (schematic designator C8)
C9 "GCM155R71C104KA55D" 0402 297.71,761.49 r90 bottom locked value=0.1uF
C10 "GCM21BR71A106KE22L" 0805L 522.33,1259.8 r0 bottom locked value=10uF
C11 "GCM31CR71A226KE02" 1206_180L 173.03,1240.08 r180 bottom locked value=22uF
C12 "GCM21BR71A106KE22L" 0805L 178.04,1160.14 r180 bottom locked value=10uF
C13 "GCM188R71C105KA64J" 0603S 173.04,1099.98 r180 bottom locked value=1uF
C14 "GCM21BR71A106KE22L" 0805L 522.33,2193.13 r0 bottom locked value=10uF
C15 "GCM31CR71A226KE02" 1206_180L 173.03,2190.59 r180 bottom locked value=22uF
C16 "GCM21BR71A106KE22L" 0805L 178.04,2110.65 r180 bottom locked value=10uF
C17 "GCM188R71C105KA64J" 0603S 173.04,2050.48 r180 bottom locked value=1uF
C18 "GCM31CR71A226KE02" 1206_180L 414.55,2785.62 r90 bottom locked value=22uF
C19 "GCM21BR71A106KE22L" 0805L 332.11,2762.78 r90 bottom locked value=10uF
C20 "GCM188R71C105KA64J" 0603S 265.9,2763.05 r90 bottom locked value=1uF
C21 "GCM31CR71A226KE02" 1206_180L 217.55,1428.37 r90 bottom locked value=22uF
C22 "GCM31CR71A226KE02" 1206_180L 962.95,1403.1 r90 bottom locked value=22uF
C23 "GCM21BR71A106KE22L" 0805L 1049.07,1401.66 r90 bottom locked value=10uF
C24 "GCM31CR71A226KE02" 1206_180L 994.04,1240.08 r0 bottom locked value=22uF
C25 "GCM21BR71A106KE22L" 0805L 644.75,1332.8 r180 bottom locked value=10uF
C26 "GCM188R71C105KA64J" 0603S 1116.49,1399.97 r90 bottom locked value=1uF
C27 "GCM21BR71A106KE22L" 0805L 644.75,1259.8 r180 bottom locked value=10uF
C28 "GCM188R71C105KA64J" 0603S 994.03,1099.98 r0 bottom locked value=1uF
C29 "GCM21BR71A106KE22L" 0805L 135.75,1452 r90 bottom locked value=10uF
C30 "GCM31CR71A226KE02" 1206_180L 994.04,2285.85 r0 bottom locked value=22uF
C31 "GCM21BR71A106KE22L" 0805L 989.03,2365.79 r0 bottom locked value=10uF
C32 "GCM21BR71A106KE22L" 0805L 989.03,1160.14 r0 bottom locked value=10uF
C33 "GCM21BR71A106KE22L" 0805L 644.75,2266.12 r180 bottom locked value=10uF
C34 "GCM188R71C105KA64J" 0603S 994.03,2425.95 r0 bottom locked value=1uF
C35 "GCM21BR71A106KE22L" 0805L 644.75,2193.13 r180 bottom locked value=10uF
C36 "GCM188R71C105KA64J" 0603S 1095.23,2080.31 r270 bottom locked value=1uF
C37 "GCM155R71H391KA37D" 0402S 733.8,1591.98 r0 bottom locked value=390pF
C38 "GCM155R71H391KA37D" 0402S 433.28,1591.98 r180 bottom locked value=390pF
C39 "GCM188R72A682KA37D" 0603S 608.24,1505.01 r90 top locked value=6800pF
C40 "GRM21BR60J107M" 0805L 643.44,1716.98 r180 top locked value=100uF
C41 "GRM21BR60J107M" 0805L 768.09,1574.81 r90 top locked value=100uF
C42 "GCM155R71C104JA55D" 0402S 643.45,1597.62 r180 top locked value=0.1uF
C43 "GRM21BR71A106KE51L" 0805L 643.44,1648.99 r180 top locked value=10uF
C44 "GCM188R72A682KA37D" 0603S 558.83,1505.01 r90 top locked value=6800pF
C45 "GRM21BR60J107M" 0805L 523.64,1716.98 r0 top locked value=100uF
C46 "GRM21BR60J107M" 0805L 398.98,1574.81 r90 top locked value=100uF
C47 "GCM155R71C104JA55D" 0402S 523.63,1597.62 r0 top locked value=0.1uF
C48 "GRM21BR71A106KE51L" 0805L 523.64,1649.43 r0 top locked value=10uF
C49 "GCM155R71H391KA37D" 0402S 733.8,1933.94 r0 bottom locked value=390pF
C50 "GCM155R71H391KA37D" 0402S 433.28,1933.94 r180 bottom locked value=390pF
C51 "GCM188R72A682KA37D" 0603S 608.24,2020.91 r270 top locked value=6800pF
C52 "GRM21BR60J107M" 0805L 643.44,1808.94 r180 top locked value=100uF
C53 "GRM21BR60J107M" 0805L 768.09,1951.12 r270 top locked value=100uF
C54 "GCM155R71C104JA55D" 0402S 643.45,1928.3 r180 top locked value=0.1uF
C55 "GRM21BR71A106KE51L" 0805L 643.44,1876.94 r180 top locked value=10uF
C56 "GCM188R72A682KA37D" 0603S 558.83,2020.91 r270 top locked value=6800pF
C57 "GRM21BR60J107M" 0805L 398.98,1951.12 r270 top locked value=100uF
C58 "GRM21BR60J107M" 0805L 523.64,1808.94 r0 top locked value=100uF
C59 "GCM155R71C104JA55D" 0402S 523.63,1928.3 r0 top locked value=0.1uF
C60 "GRM21BR71A106KE51L" 0805L 523.64,1876.94 r0 top locked value=10uF
C61 "GRM21BZ71A226ME15L" 0805L 644.75,1405.79 r180 bottom locked value=22uF
C62 "GRM21BZ71A226ME15L" 0805L 775.98,1474.81 r90 bottom locked value=22uF
C63 "GCM155R71C104JA55D" 0402S 199.53,1739.74 r180 bottom locked value=0.1uF
C64 "GRM21BZ71A226ME15L" 0805L 522.33,1405.79 r0 bottom locked value=22uF
C65 "GRM21BZ71A226ME15L" 0805L 392.43,1476.14 r90 bottom locked value=22uF
C66 "GRM21BZ71A226ME15L" 0805L 775.98,2051.12 r270 bottom locked value=22uF
C67 "GRM21BZ71A226ME15L" 0805L 644.75,2120.14 r180 bottom locked value=22uF
C68 "GRM21BZ71A226ME15L" 0805L 391.09,2051.12 r270 bottom locked value=22uF
C69 "GRM21BZ71A226ME15L" 0805L 522.33,2120.14 r0 bottom locked value=22uF
C70 "GCM21BR71A106KE22L" 0805L 5393.06,544.94 r0 bottom locked value=10uF
C71 "GCM31CR71A226KE02" 1206_180L 5091.14,662.09 r90 bottom locked value=22uF
C72 "GCM21BR71A106KE22L" 0805L 5006.37,685.13 r90 bottom locked value=10uF
C73 "GCM188R71C105KA64J" 0603S 4936.41,685.13 r90 bottom locked value=1uF
C74 "GCM21BR71A106KE22L" 0805L 5393.06,1478.27 r0 bottom locked value=10uF
C75 "GCM31CR71A226KE02" 1206_180L 5043.76,1497.99 r180 bottom locked value=22uF
C76 "GCM21BR71A106KE22L" 0805L 5048.77,1577.93 r180 bottom locked value=10uF
C77 "GCM188R71C105KA64J" 0603S 5043.77,1638.09 r180 bottom locked value=1uF
C78 "GCM188R71C105KA64J" 0603S 71.91,1451.54 r90 bottom locked value=1uF
C79 "GCM31CR71A226KE02" 1206_180L 5744.45,295.52 r270 bottom locked value=22uF
C80 "GCM21BR71A106KE22L" 0805L 5829.19,296.85 r270 bottom locked value=10uF
C81 "GCM31CR71A226KE02" 1206_180L 946.37,2084.69 r270 bottom locked value=22uF
C82 "GCM21BR71A106KE22L" 0805L 5515.47,471.95 r180 bottom locked value=10uF
C83 "GCM188R71C105KA64J" 0603S 5892.71,297.42 r270 bottom locked value=1uF
C84 "GCM21BR71A106KE22L" 0805L 5515.47,544.94 r180 bottom locked value=10uF
C85 "GCM188R71C105KA64J" 0603S 5970.63,650.66 r90 bottom locked value=1uF
C86 "GCM21BR71A106KE22L" 0805L 522.33,2266.12 r0 bottom locked value=10uF
C87 "GCM31CR71A226KE02" 1206_180L 5834.15,1283.42 r270 bottom locked value=22uF
C88 "GCM21BR71A106KE22L" 0805L 5918.7,1285.61 r270 bottom locked value=10uF
C89 "GCM21BR71A106KE22L" 0805L 1030.65,2085.79 r270 bottom locked value=10uF
C90 "GCM21BR71A106KE22L" 0805L 5515.47,1405.27 r180 bottom locked value=10uF
C91 "GCM188R71C105KA64J" 0603S 5984.53,1287.79 r270 bottom locked value=1uF
C92 "GCM21BR71A106KE22L" 0805L 5515.47,1478.27 r180 bottom locked value=10uF
C93 "GCM188R71C105KA64J" 0603S 5651.36,1947.85 r180 bottom locked value=1uF
C94 "CGA2B3X7R1H104K050BB" 0402 3564.27,4896.25 r90 top locked value=0.1uF
C95 "GCM155R71H391KA37D" 0402S 5604.52,804.13 r0 bottom locked value=390pF
C96 "GCM155R71H391KA37D" 0402S 5304,804.13 r180 bottom locked value=390pF
C97 "GCM188R72A682KA37D" 0603S 5429.56,1233.05 r270 top locked value=6800pF
C98 "GRM21BR60J107M" 0805L 5638.82,786.95 r90 top locked value=100uF
C99 "GRM21BR60J107M" 0805L 5514.16,929.12 r180 top locked value=100uF
C100 "GCM155R71C104JA55D" 0402S 5514.17,809.77 r180 top locked value=0.1uF
C101 "GRM21BR71A106KE51L" 0805L 5514.16,861.13 r180 top locked value=10uF
C102 "GCM188R72A682KA37D" 0603S 5478.97,717.16 r90 top locked value=6800pF
C103 "GRM21BR60J107M" 0805L 5269.71,786.95 r90 top locked value=100uF
C104 "GRM21BR60J107M" 0805L 5394.36,929.12 r0 top locked value=100uF
C105 "GCM155R71C104JA55D" 0402S 5394.35,809.77 r0 top locked value=0.1uF
C106 "GRM21BR71A106KE51L" 0805L 5394.36,861.58 r0 top locked value=10uF
C107 "GCM155R71H391KA37D" 0402S 5604.52,1146.09 r0 bottom locked value=390pF
C108 "GCM155R71H391KA37D" 0402S 5304,1146.09 r180 bottom locked value=390pF
C109 "GCM188R72A682KA37D" 0603S 5429.56,717.16 r90 top locked value=6800pF
C110 "GRM21BR60J107M" 0805L 5638.82,1163.26 r270 top locked value=100uF
C111 "GRM21BR60J107M" 0805L 5514.16,1021.09 r180 top locked value=100uF
C112 "GCM155R71C104JA55D" 0402S 5514.17,1140.45 r180 top locked value=0.1uF
C113 "GRM21BR71A106KE51L" 0805L 5514.16,1089.08 r180 top locked value=10uF
C114 "GCM188R72A682KA37D" 0603S 5478.97,1233.05 r270 top locked value=6800pF
C115 "GRM21BR60J107M" 0805L 5269.71,1163.26 r270 top locked value=100uF
C116 "GRM21BR60J107M" 0805L 5394.36,1021.09 r0 top locked value=100uF
C117 "GCM155R71C104JA55D" 0402S 5394.35,1140.45 r0 top locked value=0.1uF
C118 "GRM21BR71A106KE51L" 0805L 5394.36,1089.08 r0 top locked value=10uF
C119 "GRM21BZ71A226ME15L" 0805L 5515.47,617.93 r180 bottom locked value=22uF
C120 "GRM21BZ71A226ME15L" 0805L 5646.71,686.95 r90 bottom locked value=22uF
C121 "GCM155R71C104JA55D" 0402S 5070.26,956.89 r180 bottom locked value=0.1uF
C122 "GRM21BZ71A226ME15L" 0805L 5393.06,617.93 r0 bottom locked value=22uF
C123 "GRM21BZ71A226ME15L" 0805L 5263.16,688.29 r90 bottom locked value=22uF
C124 "GRM21BZ71A226ME15L" 0805L 5646.71,1263.26 r270 bottom locked value=22uF
C125 "GRM21BZ71A226ME15L" 0805L 5515.47,1332.28 r180 bottom locked value=22uF
C126 "GRM21BZ71A226ME15L" 0805L 5261.82,1263.26 r270 bottom locked value=22uF
C127 "GRM21BZ71A226ME15L" 0805L 5393.06,1332.28 r0 bottom locked value=22uF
